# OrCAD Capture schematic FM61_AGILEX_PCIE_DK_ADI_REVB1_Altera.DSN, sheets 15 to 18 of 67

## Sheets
15 DDR4/DDRT Single DIMM CH2: size B
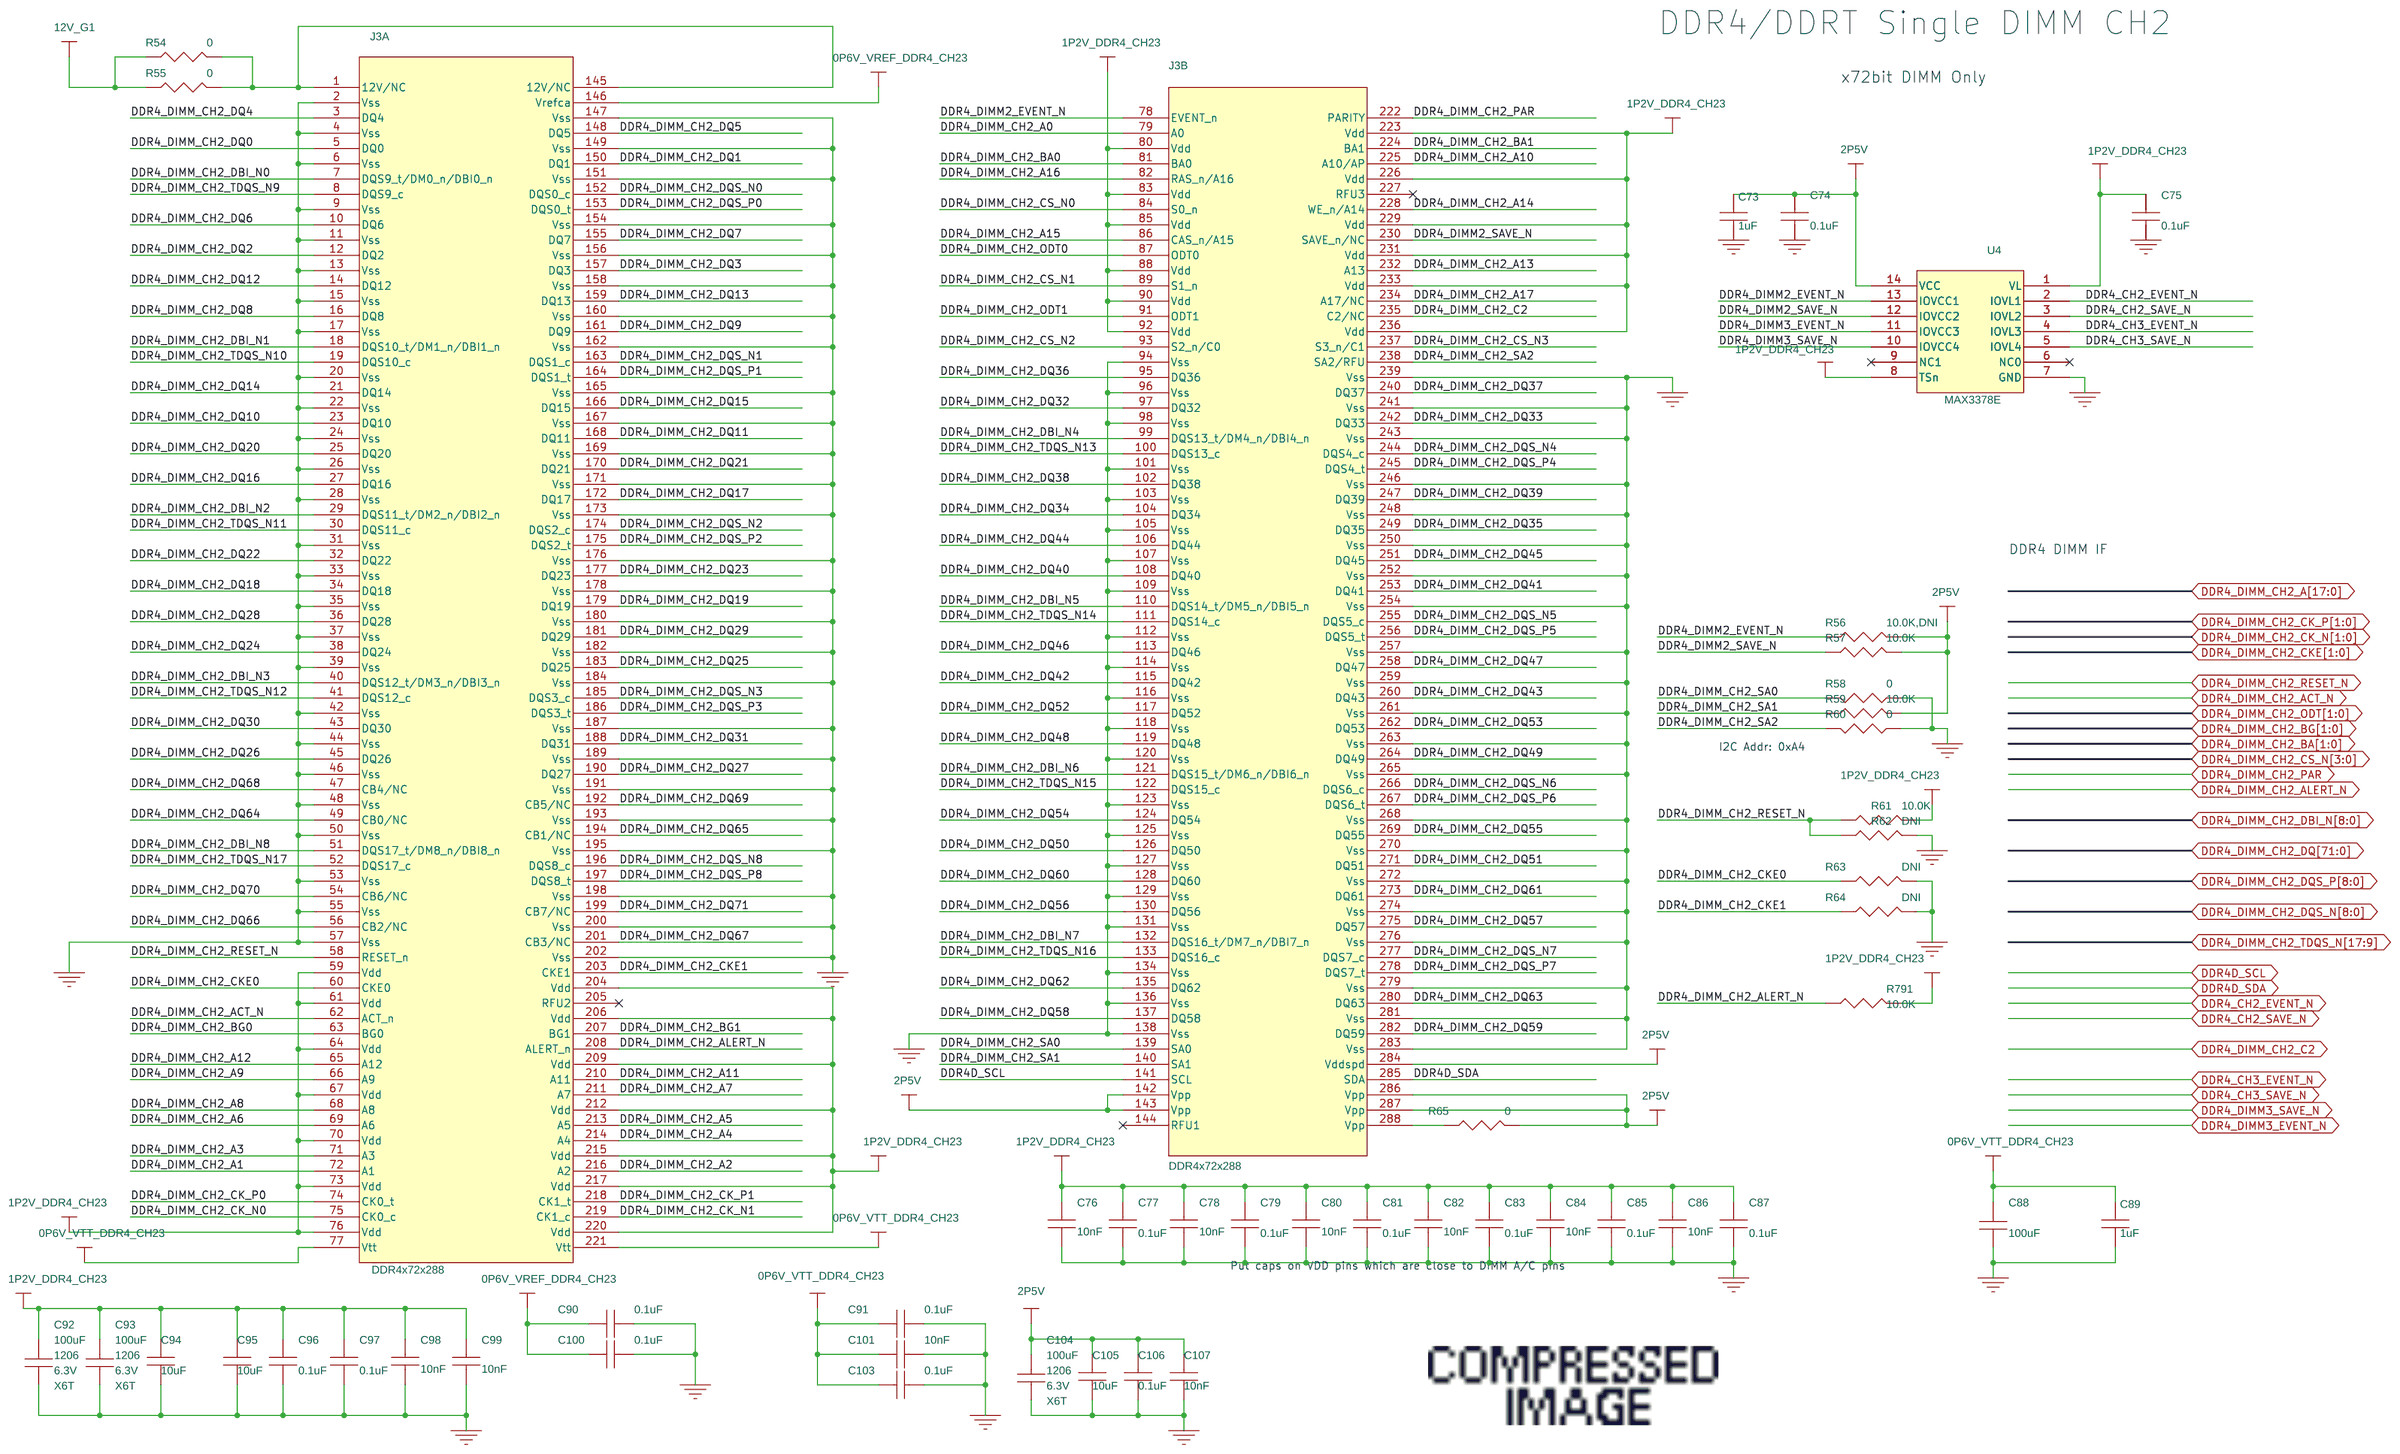
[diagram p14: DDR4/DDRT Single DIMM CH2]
16 FPGA BANK 2A: size B
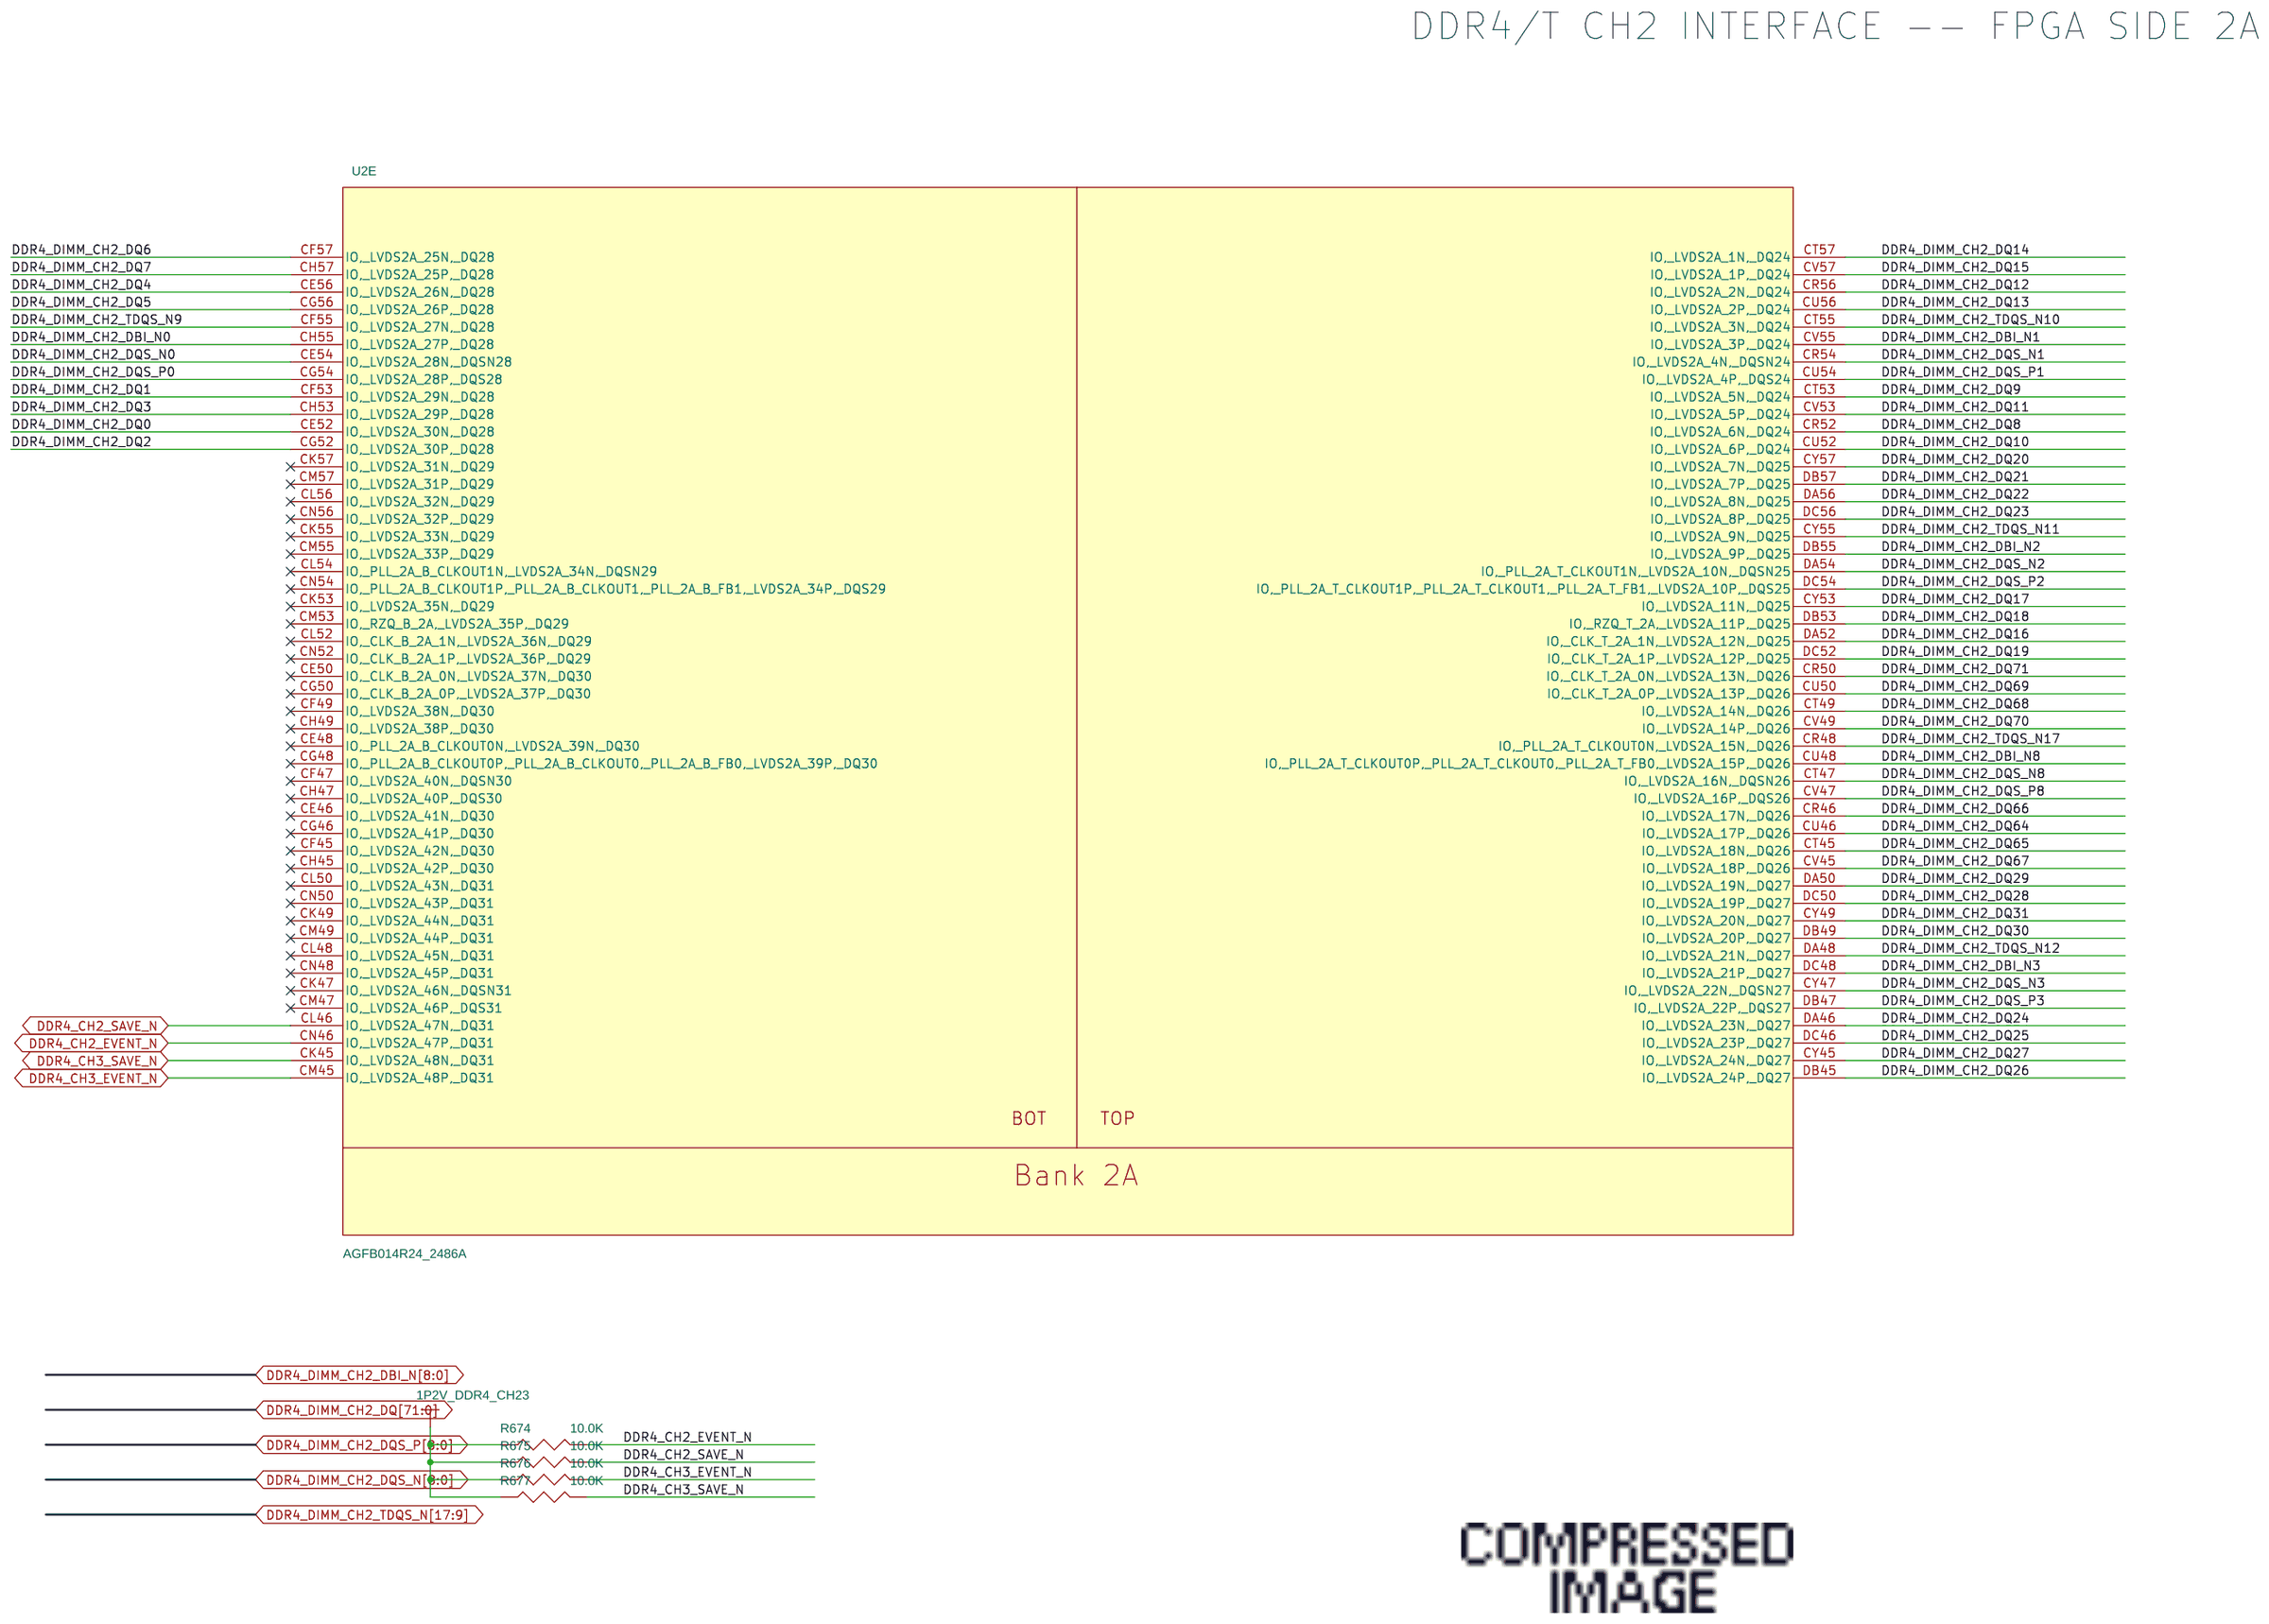
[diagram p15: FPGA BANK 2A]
17 FPGA BANK 2B: size B
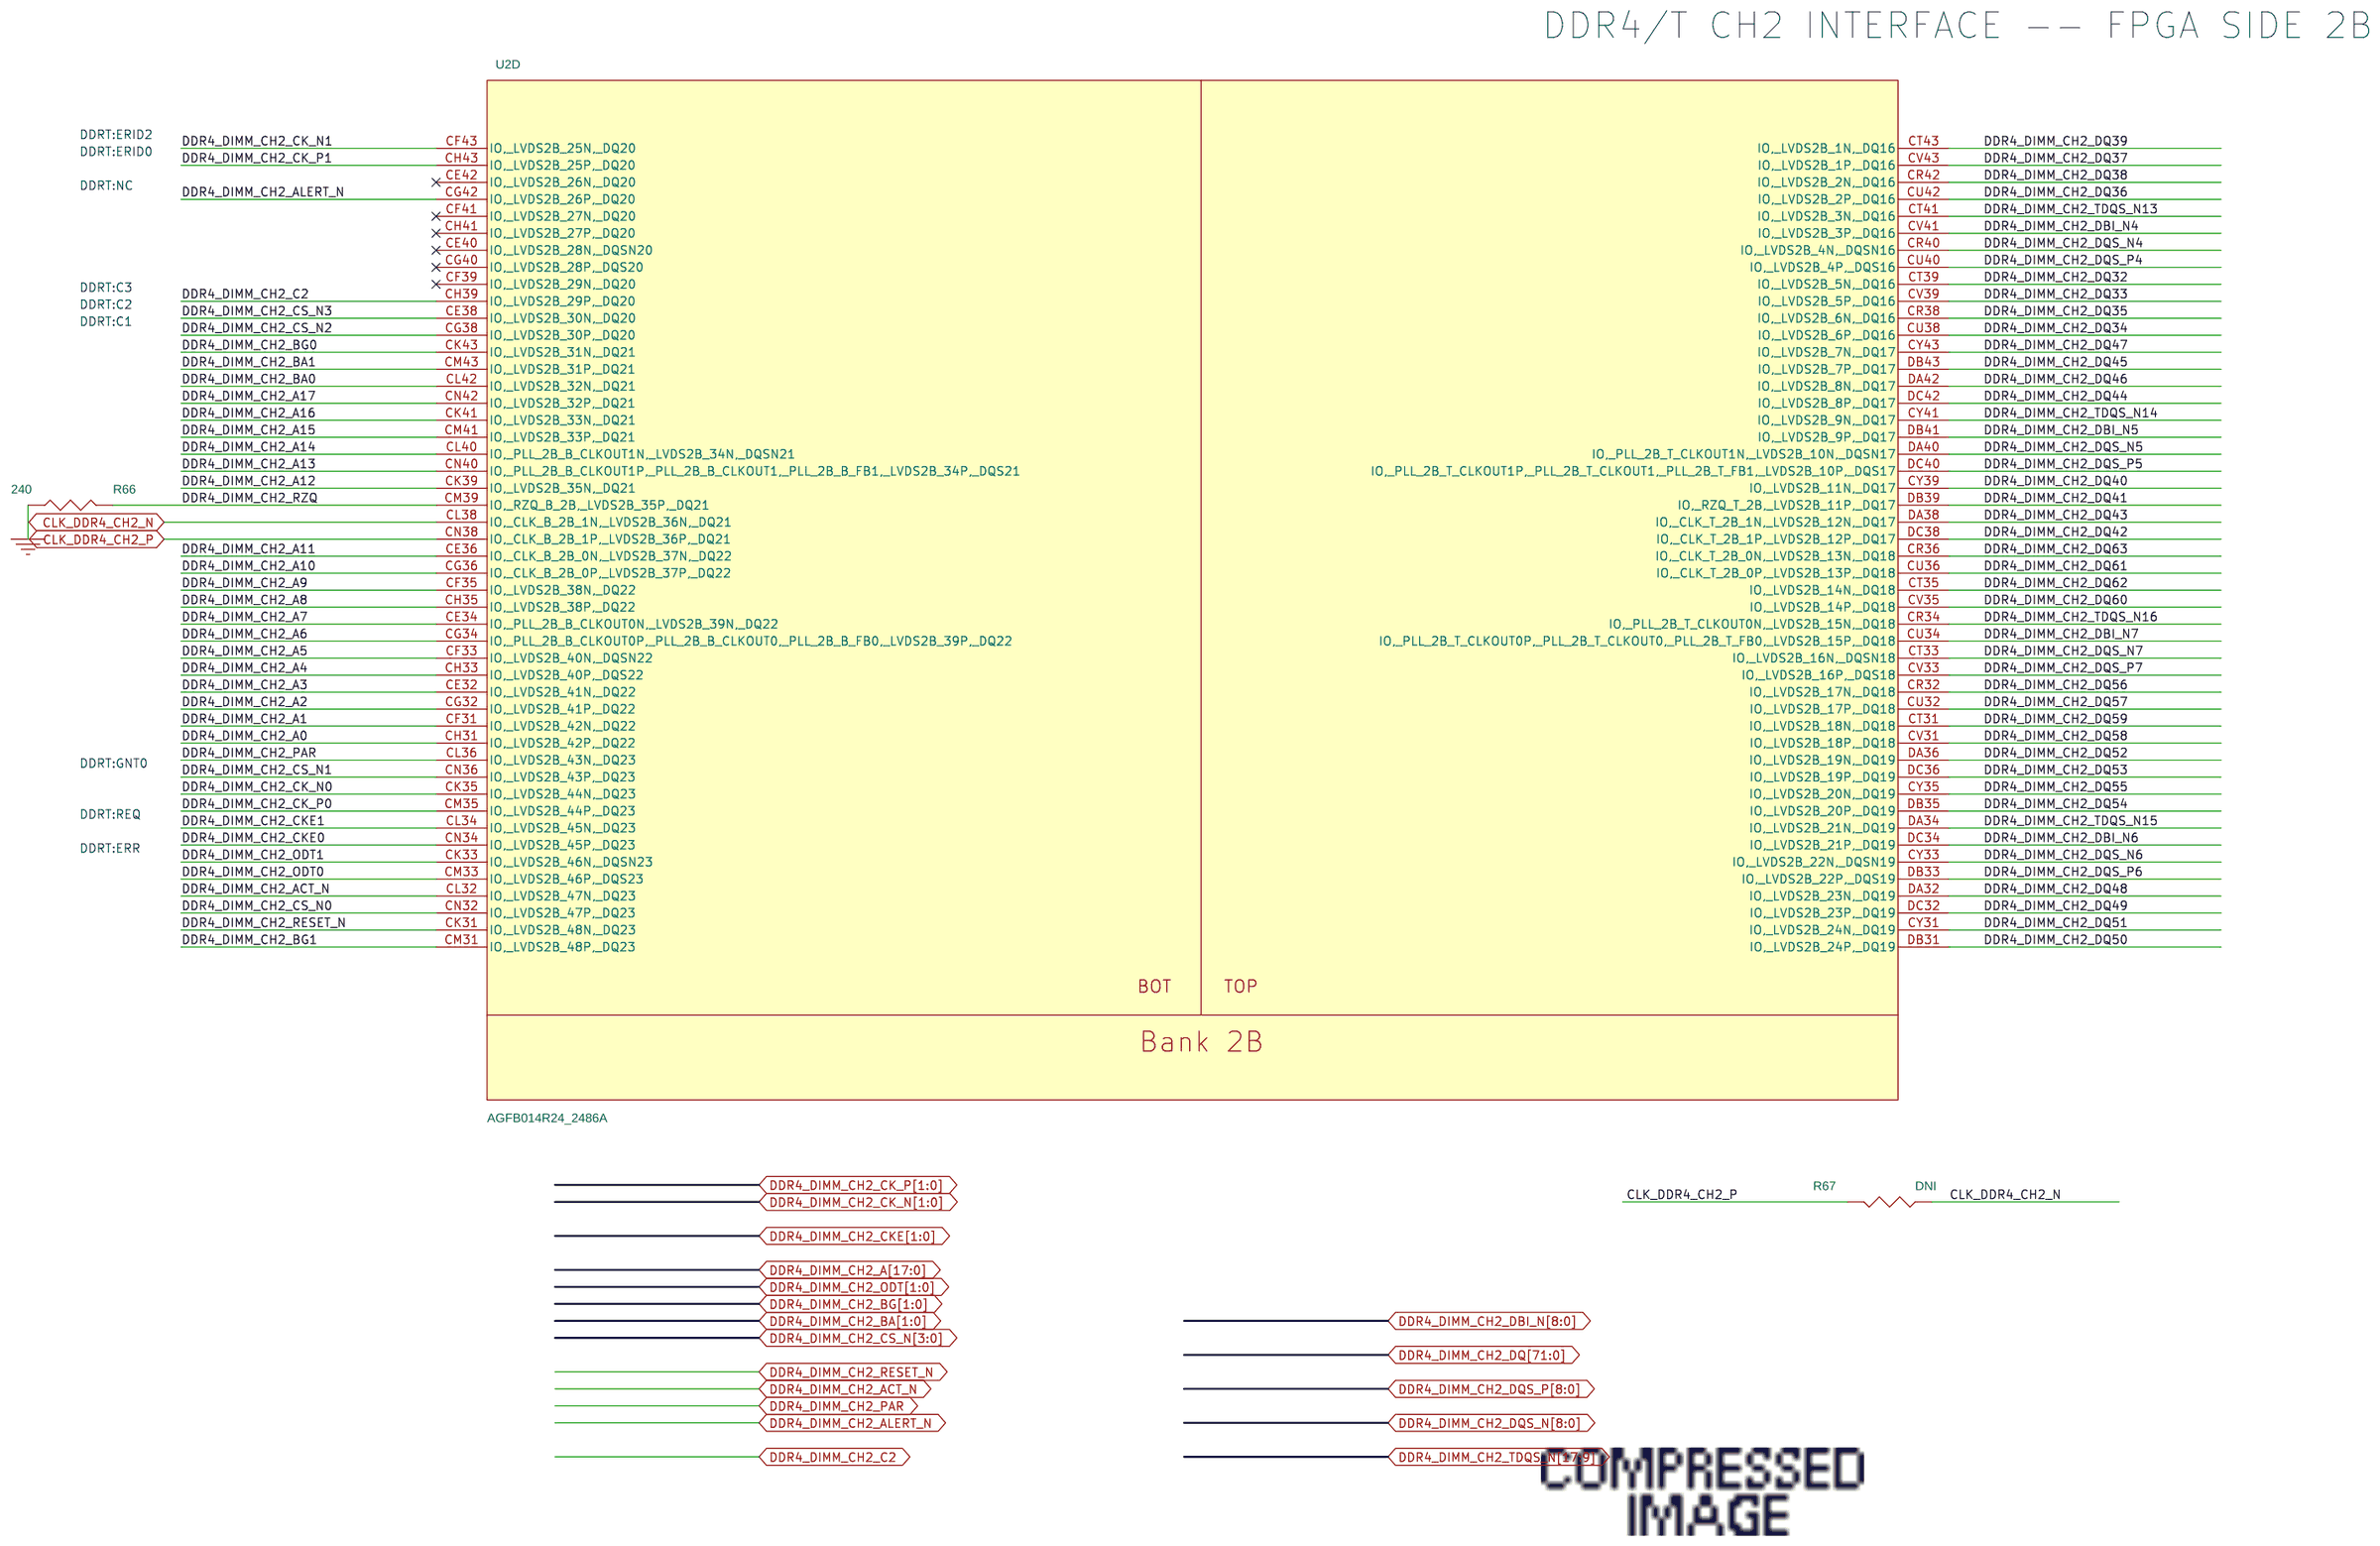
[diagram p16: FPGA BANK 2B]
18 DDR4/DDRT Single DIMM CH3: size B
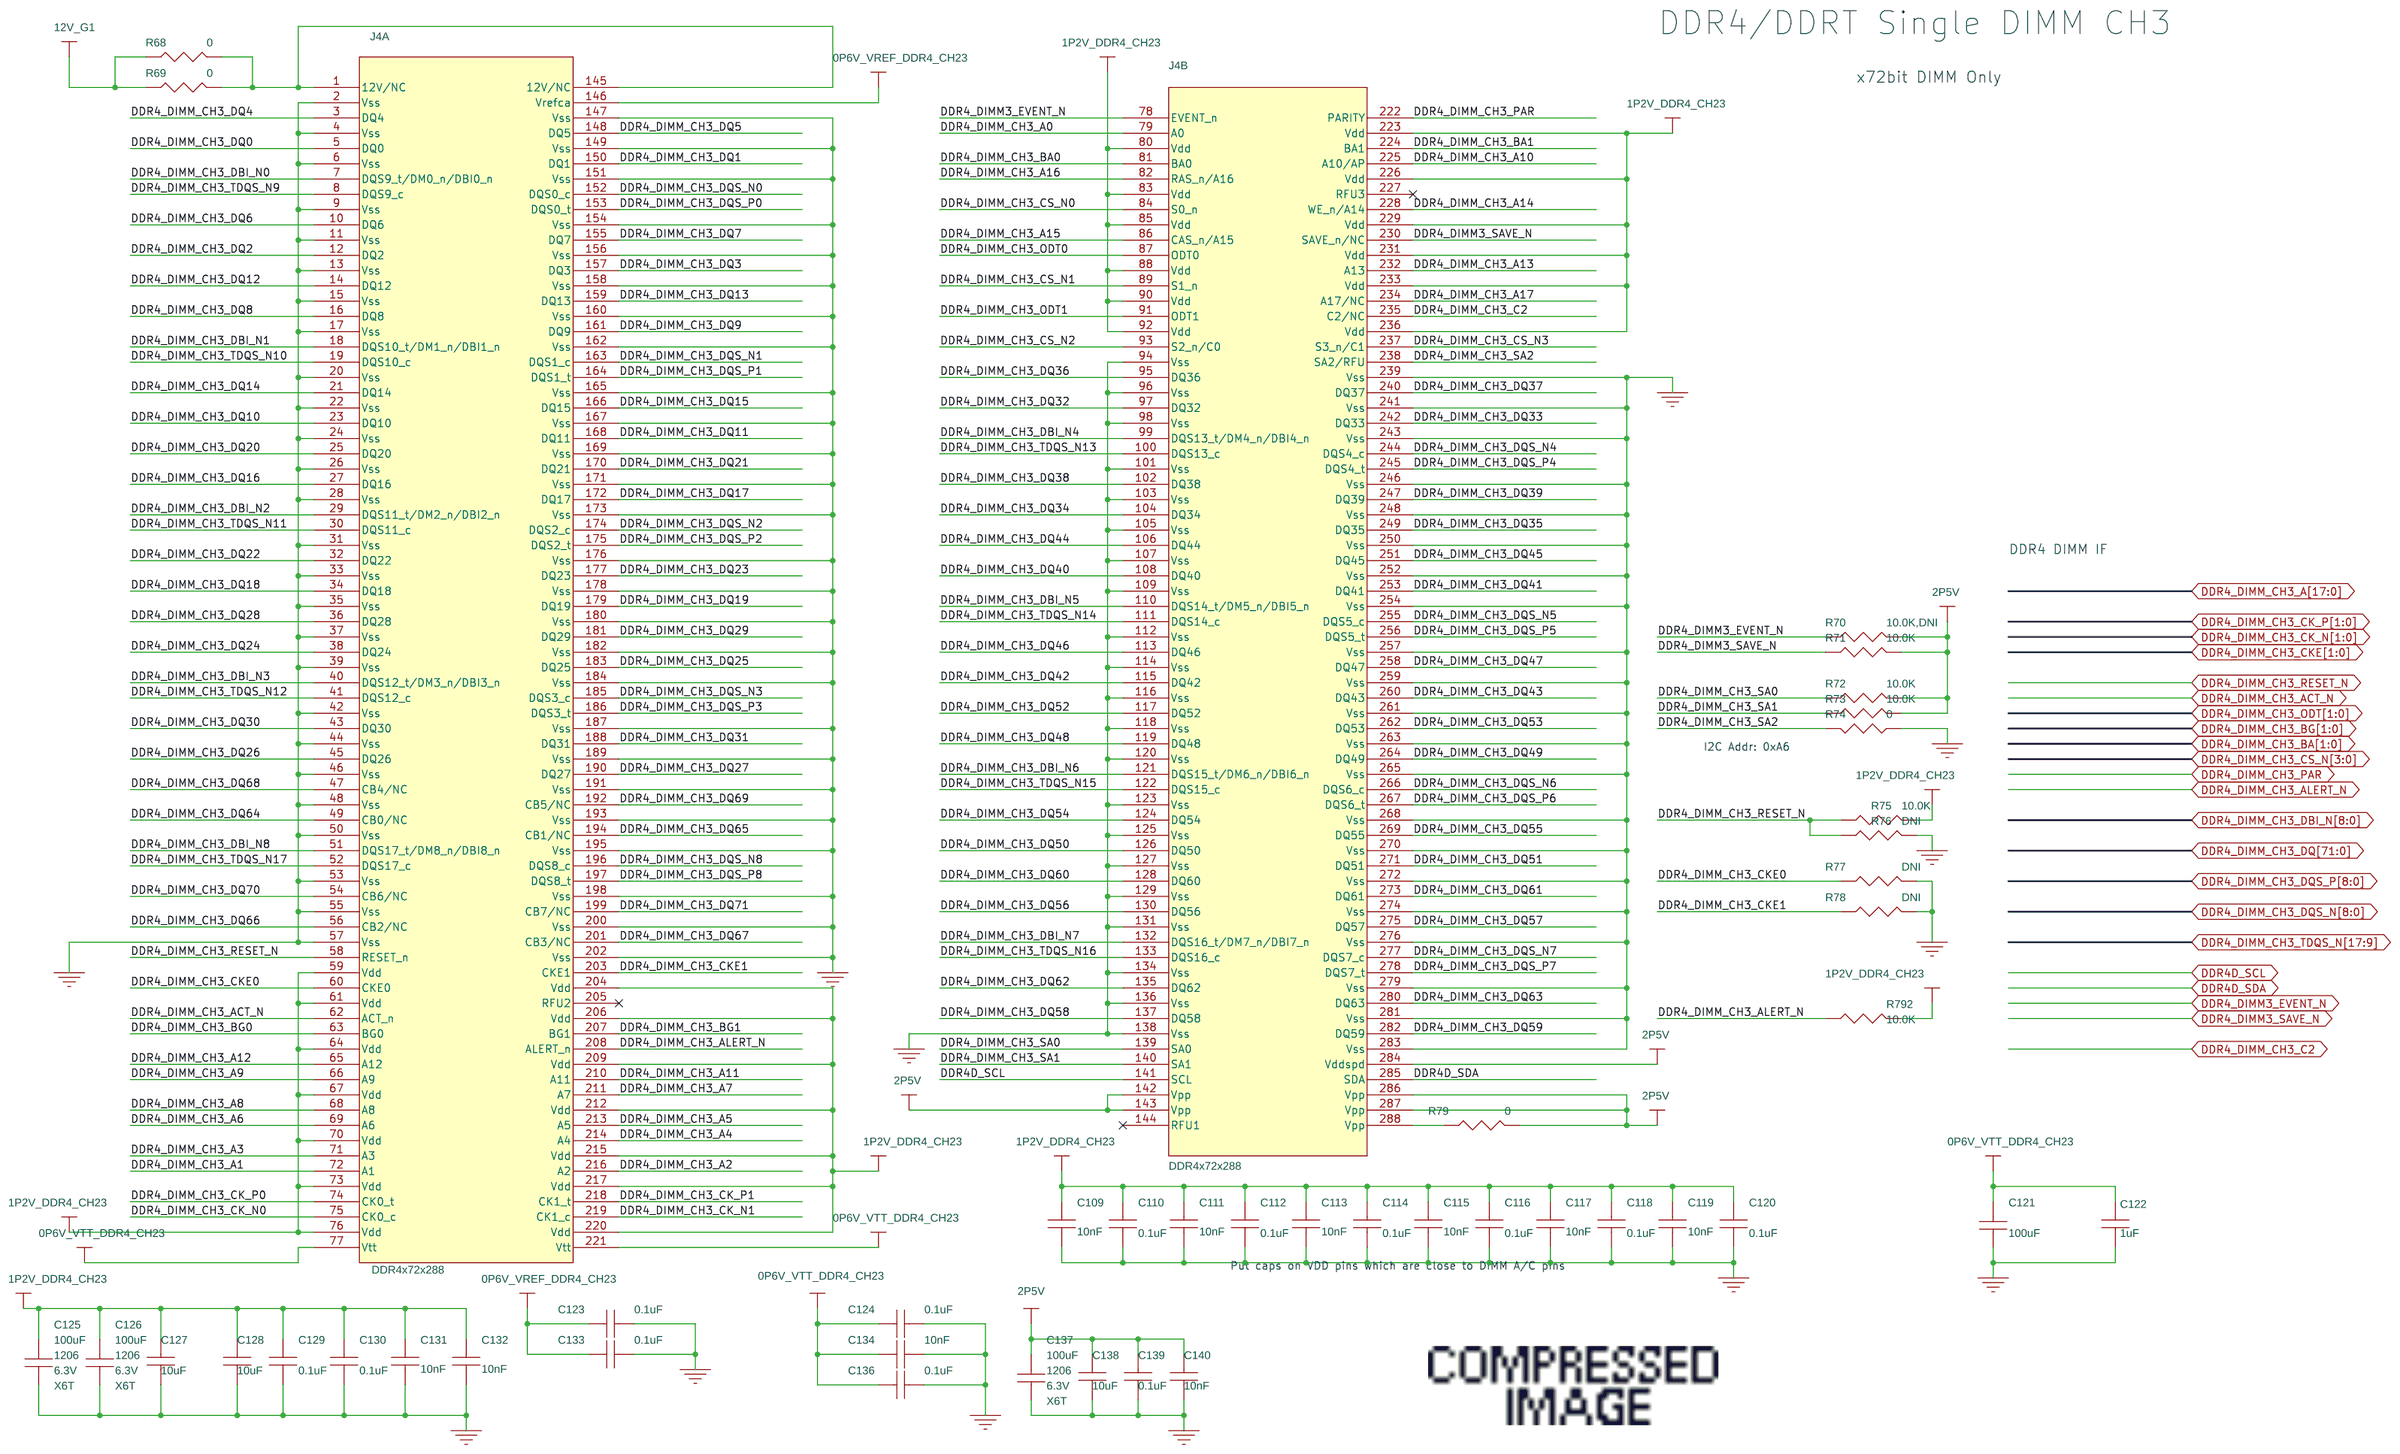
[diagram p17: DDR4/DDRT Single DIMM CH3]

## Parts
sheet DDR4/DDRT Single DIMM CH2
C73  1uF  [0402]
C74  0.1uF  [0402]
C75  0.1uF  [0402]
C76  10nF  [0402]
C77  0.1uF  [0402]
C78  10nF  [0402]
C79  0.1uF  [0402]
C80  10nF  [0402]
C81  0.1uF  [0402]
C82  10nF  [0402]
C83  0.1uF  [0402]
C84  10nF  [0402]
C85  0.1uF  [0402]
C86  10nF  [0402]
C87  0.1uF  [0402]
C88  100uF  [1206]
C89  1uF  [0402]
C90  0.1uF  [0402]
C91  0.1uF  [0402]
C92  100uF  [1206]
C93  100uF  [1206]
C94  10uF  [1210]
C95  10uF  [1210]
C96  0.1uF  [0402]
C97  0.1uF  [0402]
C98  10nF  [0402]
C99  10nF  [0402]
C100  0.1uF  [0402]
C101  10nF  [0402]
C103  0.1uF  [0402]
C104  100uF  [1206]
C105  10uF  [1210]
C106  0.1uF  [0402]
C107  10nF  [0402]
J3  DDR4x72x288  [DDR4DIMM_SMT]  (sections A,B)
R54  0  [1206]
R55  0  [1206]
R56  10.0K,DNI  [0402]
R57  10.0K  [0402]
R58  0  [0402]
R59  10.0K  [0402]
R60  0  [0402]
R61  10.0K  [0402]
R62  DNI  [0402]
R63  DNI  [0402]
R64  DNI  [0402]
R65  0  [0603]
R791  10.0K  [0402]
U4  MAX3378E  [TSSOP-14]
sheet DDR4/DDRT Single DIMM CH3
C109  10nF  [0402]
C110  0.1uF  [0402]
C111  10nF  [0402]
C112  0.1uF  [0402]
C113  10nF  [0402]
C114  0.1uF  [0402]
C115  10nF  [0402]
C116  0.1uF  [0402]
C117  10nF  [0402]
C118  0.1uF  [0402]
C119  10nF  [0402]
C120  0.1uF  [0402]
C121  100uF  [1206]
C122  1uF  [0402]
C123  0.1uF  [0402]
C124  0.1uF  [0402]
C125  100uF  [1206]
C126  100uF  [1206]
C127  10uF  [1210]
C128  10uF  [1210]
C129  0.1uF  [0402]
C130  0.1uF  [0402]
C131  10nF  [0402]
C132  10nF  [0402]
C133  0.1uF  [0402]
C134  10nF  [0402]
C136  0.1uF  [0402]
C137  100uF  [1206]
C138  10uF  [1210]
C139  0.1uF  [0402]
C140  10nF  [0402]
J4  DDR4x72x288  [DDR4DIMM_SMT]  (sections A,B)
R68  0  [1206]
R69  0  [1206]
R70  10.0K,DNI  [0402]
R71  10.0K  [0402]
R72  10.0K  [0402]
R73  10.0K  [0402]
R74  0  [0402]
R75  10.0K  [0402]
R76  DNI  [0402]
R77  DNI  [0402]
R78  DNI  [0402]
R79  0  [0603]
R792  10.0K  [0402]
sheet FPGA BANK 2A
R674  10.0K  [0402]
R675  10.0K  [0402]
R676  10.0K  [0402]
R677  10.0K  [0402]
sheet FPGA BANK 2B
R66  240  [0402]
R67  DNI  [0402]
sheet FPGA Gnd 2
U2  AGFB014R24_2486A  [FBGA2486A_HEX]  (sections A,B,C,D,E,F,G,H,I,J,K,L,M,N,O,P,Q,R,S,T,U,V,W,X)

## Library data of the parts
C73 C89 C122 = CAP: CAP, X5R, 1UF, 20%, 10V, 0402,; IPN: H67656-001; Item Num: P03-15479R; Lead Free Status: Yes; Manufacturer: Murata; Manufacturer Part Num: GRM155R61A105KE15D; Num Pins: 2; Part Class: CAPACITORS; RoHS Compliant: Yes; Voltage: 10V
C74 C75 C77 C79 C81 C83 C85 C87 C90 C91 C96 C97 C100 C103 C106 C110 C112 C114 C116 C118 C120 C123 C124 C129 C130 C133 C136 C139 = CAP: CAPC,Y5V,0402,0.1UF,25V,+80/-20%; Dielectric: Y5V; IPN: K13560-001; Item Num: P03-15057R; LIFECYCLE_PHASE: Active; Lead Free Status: Lead Free; MFR_LIFECYCLE: Active; Manufacturer: Murata; Manufacturer Part Num: GRM155F51E104ZA01D; Num Pins: 2; PART_SUBCLASS: CAPACITORS; Part Class: CAPACITORS; RATED_VOLTAGE: 25V; RoHS Compliant: RoHS Compliant; Tolerance: +80%/-20%
C76 C78 C84 C86 C98 C99 C109 C111 C113 C115 C117 C119 C131 C134 C140 = Cap_10000PF_50V_0402: CAP - CERAMIC, 10nF, 0402, 50V, Y5V; IPN: K30697-001; IPN No: K30697-001; Item Num: P03-15058R; Manufacturer Part Num: GRM155F51H103Z
C80 C82 C101 C107 C132 = Cap_10000PF_50V_0402: CAP - CERAMIC, 10nF, 0402, 50V, Y5V; IPN: K30697-001; Item Num: P03-15058R; Manufacturer Part Num: GRM155F51H103Z
C88 C92 C93 C104 C121 C125 C126 C137 = CAP: CAP CER 100UF 6.3V X6T 1206; AGILE_LINK: http://sj-agile9app/Agile/PLMServlet?action=OpenEmailObject&classid=10000&objid=257560276; IPN: H65271-004; Item Num: P03-18002R; LIFECYCLE_PHASE: Active; Lead Free Status: Lead Free; MFR_LIFECYCLE: Active; Manufacturer: Murata; Manufacturer Part Num: GRM31CD80J107ME39L; Num Pins: 2; PART_SUBCLASS: CAPACITORS; RATED_VOLTAGE: 6.3V; RoHS Compliant: RoHS Compliant; TOLERANCE: 20%; Temperature Coefficient: X6T
C94 C95 C105 C127 C128 C138 = CAP_10uF_+_-10%_25V_1210: CAP - CER, 10UF, 25V, 10%, X7R, 1210; Agile Part Description: CAP - CER, 10UF, 25V, 10%, X7R, 1210; IPN: G10603-003; Item Num: P03-15392R; Manufacturer Part Num: GRM32DR71E106KA12L
J3 J4 = DDR4x72x288_1: CONN SMT DDR4 288POS VERT; COMPGROUP: DDR4_PINGPONG_DIMMA; IPN: K21528-001; Item Num: P23-38871R; Manufacturer: Molex Inc; Manufacturer Part Num: 787301002
R54 R55 R68 R69 = RESISTOR: RES SMD 0 OHM JUMPER 3/4W 1206; AGILE_LINK: http://sj-agile9app/Agile/PLMServlet?action=OpenEmailObject&classid=10000&objid=146548997; IPN: A93552-015; Item Num: P02-17994R; LIFECYCLE_PHASE: Active; Lead Free Status: No; MFR_LIFECYCLE: Active; Manufacturer: Vishay Dale; Manufacturer Part Num: CRCW12060000Z0EAHP; Num Pins: 2; PART_SUBCLASS: RESISTORS; POWER: 3/4W; RoHS Compliant: Yes; TOLERANCE: +/-1%
R56 R70 = RESISTOR: RES,10.0K OHMS,1.0%,1/16W, 0402; AGILE_LINK: http://sj-agile9app/Agile/PLMServlet?action=OpenEmailObject&classid=10000&objid=146548997; IPN: A93548-034; Item Num: P02-11364R; LIFECYCLE_PHASE: Active; Lead Free Status: No; MFR_LIFECYCLE: Active; Manufacturer: Panasonic; Manufacturer Part Num: ERJ-2RKF1002X; Num Pins: 2; PART_SUBCLASS: RESISTORS; POWER: 1/16W; RESISTANCE: 10.0K; RoHS Compliant: Yes; TOLERANCE: +/-1%
R57 R59 R61 R71-R73 R75 R674-R677 R791 R792 = RESISTOR: RES,10.0K OHMS,1.0%,1/16W, 0402; AGILE_LINK: http://sj-agile9app/Agile/PLMServlet?action=OpenEmailObject&classid=10000&objid=146548997; IPN: A93548-034; Item Num: P02-11364R; LIFECYCLE_PHASE: Active; Lead Free Status: No; MFR_LIFECYCLE: Active; Manufacturer: Panasonic; Manufacturer Part Num: ERJ-2RKF1002X; Num Pins: 2; PART_SUBCLASS: RESISTORS; POWER: 1/16W; RoHS Compliant: Yes; TOLERANCE: +/-1%
R58 R60 R74 = RES_0_OHM_5%_1_16W_0402_SMD: IPN: H30887-001
R62-R64 R76-R78 = RESISTOR: RES ZERO OHM 1/16W 5% 0402 SMD; IPN: H30887-001; Item Num: P02-14020R; Lead Free Status: No; Manufacturer: Panasonic; Manufacturer Part Num: ERJ-2GE0R00X; Num Pins: 2; Part Class: RESISTORS; Price: 0; RoHS Compliant: Yes; Tolerance: 5%
R65 R79 = RESISTOR: RES - 0 OHM, 5% 0603 1/10W; IPN: E57868-001; Item Num: P02-14007R; Lead Free Status: No; Manufacturer: Panasonic; Manufacturer Part Num: ERJ-3GEY0R00V; Num Pins: 2; Part Class: RESISTORS; RoHS Compliant: Yes; Tolerance: 5%
U4 = MAX3378E_0: IC - QUAD LOW-VOLTAGE LEVEL TRANSLATOR, +/- 15KV, ESD-PROTECTED, 1UA, 16MBPS; IPN: C34337-001; Item Num: P01-13191R; Manufacturer: Maxim; Manufacturer Part Num: MAX3378EEUD
R66 = RESISTOR: RES - 240 OHM, 1/16W, 1%, 0402 SMD; IPN: K15783-001; Item Num: P02-15995R; LIFECYCLE_PHASE: Active; Lead Free Status: Lead Free; MFR_LIFECYCLE: Active; Manufacturer: Panasonic; Manufacturer Part Num: ERJ-2RKF2400X; Num Pins: 2; PART_SUBCLASS: RESISTORS; RoHS Compliant: RoHS Compliant
R67 = RESISTOR: RES,100 OHMS,1.0%,1/16W,0402; IPN: A36092-043; Item Num: P02-11381R; Lead Free Status: No; Manufacturer: Panasonic; Manufacturer Part Num: ERJ-2RKF1000X; Manufacturer's Part No.: ERJ-2RKF1000X; Num Pins: 2; Part Class: RESISTORS; Price: 0; RoHS Compliant: Yes
U2 = FM6_2486A_V1.5: IPN: 99AH52

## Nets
12V_G1: R54.1 R55.1 R68.1 R69.1 ; also on sheet 9 12 47 48 51 52 53 58
GND: C73.2 C74.2 C75.2 C76.2 C77.2 C78.2 C79.2 C80.2 C81.2 C82.2 C83.2 C84.2 C85.2 C86.2 C87.2 C88.1 C89.2 C90.2 C91.2 C92.1 C93.1 C94.2 C95.2 C96.2 C97.2 C98.2 C99.2 C100.2 C101.2 C103.2 C104.1 C105.2 C106.2 C107.2 C109.2 C110.2 C111.2 C112.2 C113.2 C114.2 C115.2 C116.2 C117.2 C118.2 C119.2 C120.2 C121.1 C122.2 C123.2 C124.2 C125.1 C126.1 C127.2 C128.2 C129.2 C130.2 C131.2 C132.2 C133.2 C134.2 C136.2 C137.1 C138.2 C139.2 C140.2 J3.2(Vss) J3.4(Vss) J3.6(Vss) J3.9(Vss) J3.11(Vss) J3.13(Vss) J3.15(Vss) J3.17(Vss) J3.20(Vss) J3.22(Vss) J3.24(Vss) J3.26(Vss) J3.28(Vss) J3.31(Vss) J3.33(Vss) J3.35(Vss) J3.37(Vss) J3.39(Vss) J3.42(Vss) J3.44(Vss) J3.46(Vss) J3.48(Vss) J3.50(Vss) J3.53(Vss) J3.55(Vss) J3.57(Vss) J3.94(Vss) J3.96(Vss) J3.98(Vss) J3.101(Vss) J3.103(Vss) J3.105(Vss) J3.107(Vss) J3.109(Vss) J3.112(Vss) J3.114(Vss) J3.116(Vss) J3.118(Vss) J3.120(Vss) J3.123(Vss) J3.125(Vss) J3.127(Vss) J3.129(Vss) J3.131(Vss) J3.134(Vss) J3.136(Vss) J3.138(Vss) J3.147(Vss) J3.149(Vss) J3.151(Vss) J3.154(Vss) J3.156(Vss) J3.158(Vss) J3.160(Vss) J3.162(Vss) J3.165(Vss) J3.167(Vss) J3.169(Vss) J3.171(Vss) J3.173(Vss) J3.176(Vss) J3.178(Vss) J3.180(Vss) J3.182(Vss) J3.184(Vss) J3.187(Vss) J3.189(Vss) J3.191(Vss) J3.193(Vss) J3.195(Vss) J3.198(Vss) J3.200(Vss) J3.202(Vss) J3.239(Vss) J3.241(Vss) J3.243(Vss) J3.246(Vss) J3.248(Vss) J3.250(Vss) J3.252(Vss) J3.254(Vss) J3.257(Vss) J3.259(Vss) J3.261(Vss) J3.263(Vss) J3.265(Vss) J3.268(Vss) J3.270(Vss) J3.272(Vss) J3.274(Vss) J3.276(Vss) J3.279(Vss) J3.281(Vss) J3.283(Vss) J4.2(Vss) J4.4(Vss) J4.6(Vss) J4.9(Vss) J4.11(Vss) J4.13(Vss) J4.15(Vss) J4.17(Vss) J4.20(Vss) J4.22(Vss) J4.24(Vss) J4.26(Vss) J4.28(Vss) J4.31(Vss) J4.33(Vss) J4.35(Vss) J4.37(Vss) J4.39(Vss) J4.42(Vss) J4.44(Vss) J4.46(Vss) J4.48(Vss) J4.50(Vss) J4.53(Vss) J4.55(Vss) J4.57(Vss) J4.94(Vss) J4.96(Vss) J4.98(Vss) J4.101(Vss) J4.103(Vss) J4.105(Vss) J4.107(Vss) J4.109(Vss) J4.112(Vss) J4.114(Vss) J4.116(Vss) J4.118(Vss) J4.120(Vss) J4.123(Vss) J4.125(Vss) J4.127(Vss) J4.129(Vss) J4.131(Vss) J4.134(Vss) J4.136(Vss) J4.138(Vss) J4.147(Vss) J4.149(Vss) J4.151(Vss) J4.154(Vss) J4.156(Vss) J4.158(Vss) J4.160(Vss) J4.162(Vss) J4.165(Vss) J4.167(Vss) J4.169(Vss) J4.171(Vss) J4.173(Vss) J4.176(Vss) J4.178(Vss) J4.180(Vss) J4.182(Vss) J4.184(Vss) J4.187(Vss) J4.189(Vss) J4.191(Vss) J4.193(Vss) J4.195(Vss) J4.198(Vss) J4.200(Vss) J4.202(Vss) J4.239(Vss) J4.241(Vss) J4.243(Vss) J4.246(Vss) J4.248(Vss) J4.250(Vss) J4.252(Vss) J4.254(Vss) J4.257(Vss) J4.259(Vss) J4.261(Vss) J4.263(Vss) J4.265(Vss) J4.268(Vss) J4.270(Vss) J4.272(Vss) J4.274(Vss) J4.276(Vss) J4.279(Vss) J4.281(Vss) J4.283(Vss) R58.1 R60.1 R62.1 R63.1 R64.1 R66.1 R74.1 R76.1 R77.1 R78.1 U4.7(GND) ; also on sheet 9 11 12 13 14 20 21 22 23 24 25 26 28 29 30 31 32 34 35 36 37 38 39 40 41 42 43 44 45 46 47 48 49 50 51 52 53 54 55 56 57 58 59 60 61 62 63 64 65 66
0p6V_VREF_DDR4_CH23: C90.1 C100.1 C123.1 C133.1 J3.146(Vrefca) J4.146(Vrefca) ; also on sheet 34 62
0p6V_VTT_DDR4_CH23: C88.2 C89.1 C91.1 C101.1 C103.1 C121.2 C122.1 C124.1 C134.1 C136.1 J3.77(Vtt) J3.221(Vtt) J4.77(Vtt) J4.221(Vtt) ; also on sheet 62
1p2V_DDR4_CH23: C75.1 C76.1 C77.1 C78.1 C79.1 C80.1 C81.1 C82.1 C83.1 C84.1 C85.1 C86.1 C87.1 C92.2 C93.2 C94.1 C95.1 C96.1 C97.1 C98.1 C99.1 C109.1 C110.1 C111.1 C112.1 C113.1 C114.1 C115.1 C116.1 C117.1 C118.1 C119.1 C120.1 C125.2 C126.2 C127.1 C128.1 C129.1 C130.1 C131.1 C132.1 J3.59(Vdd) J3.61(Vdd) J3.64(Vdd) J3.67(Vdd) J3.70(Vdd) J3.73(Vdd) J3.76(Vdd) J3.80(Vdd) J3.83(Vdd) J3.85(Vdd) J3.88(Vdd) J3.90(Vdd) J3.92(Vdd) J3.204(Vdd) J3.206(Vdd) J3.209(Vdd) J3.212(Vdd) J3.215(Vdd) J3.217(Vdd) J3.220(Vdd) J3.223(Vdd) J3.226(Vdd) J3.229(Vdd) J3.231(Vdd) J3.233(Vdd) J3.236(Vdd) J4.59(Vdd) J4.61(Vdd) J4.64(Vdd) J4.67(Vdd) J4.70(Vdd) J4.73(Vdd) J4.76(Vdd) J4.80(Vdd) J4.83(Vdd) J4.85(Vdd) J4.88(Vdd) J4.90(Vdd) J4.92(Vdd) J4.204(Vdd) J4.206(Vdd) J4.209(Vdd) J4.212(Vdd) J4.215(Vdd) J4.217(Vdd) J4.220(Vdd) J4.223(Vdd) J4.226(Vdd) J4.229(Vdd) J4.231(Vdd) J4.233(Vdd) J4.236(Vdd) R61.2 R75.2 R674.1 R675.1 R676.1 R677.1 R791.2 R792.2 U4.1(VL) U4.8(TSn) ; also on sheet 19 25 34 46 61 62 66
2p5V: C73.1 C74.1 C104.2 C105.1 C106.1 C107.1 C137.2 C138.1 C139.1 C140.1 J3.142(Vpp) J3.143(Vpp) J3.284(Vddspd) J3.286(Vpp) J3.287(Vpp) J4.142(Vpp) J4.143(Vpp) J4.284(Vddspd) J4.286(Vpp) J4.287(Vpp) R56.2 R57.2 R59.2 R65.1 R70.2 R71.2 R72.2 R73.2 R79.1 U4.14(VCC) ; also on sheet 9 12 21 34 38 63
CLK_DDR4_CH2_N: R67.1 U2.CL38(IO,_CLK_B_2B_1N,_LVDS2B_36N,_DQ21) ; also on sheet 38
CLK_DDR4_CH2_P: R67.2 U2.CN38(IO,_CLK_B_2B_1P,_LVDS2B_36P,_DQ21) ; also on sheet 38
DDR4_CH2_EVENT_N: R674.2 U2.CN46(IO,_LVDS2A_47P,_DQ31) U4.2(IOVL1)
DDR4_CH2_SAVE_N: R675.2 U2.CL46(IO,_LVDS2A_47N,_DQ31) U4.3(IOVL2)
DDR4_CH3_EVENT_N: R676.2 U2.CM45(IO,_LVDS2A_48P,_DQ31) U4.4(IOVL3)
DDR4_CH3_SAVE_N: R677.2 U2.CK45(IO,_LVDS2A_48N,_DQ31) U4.5(IOVL4)
DDR4_DIMM2_EVENT_N: J3.78(EVENT_n) R56.1 U4.13(IOVCC1)
DDR4_DIMM2_SAVE_N: J3.230(SAVE_n/NC) R57.1 U4.12(IOVCC2)
DDR4_DIMM3_EVENT_N: J4.78(EVENT_n) R70.1 U4.11(IOVCC3)
DDR4_DIMM3_SAVE_N: J4.230(SAVE_n/NC) R71.1 U4.10(IOVCC4)
DDR4_DIMM_CH2_A0: J3.79(A0) U2.CH31(IO,_LVDS2B_42P,_DQ22)
DDR4_DIMM_CH2_A1: J3.72(A1) U2.CF31(IO,_LVDS2B_42N,_DQ22)
DDR4_DIMM_CH2_A2: J3.216(A2) U2.CG32(IO,_LVDS2B_41P,_DQ22)
DDR4_DIMM_CH2_A3: J3.71(A3) U2.CE32(IO,_LVDS2B_41N,_DQ22)
DDR4_DIMM_CH2_A4: J3.214(A4) U2.CH33(IO,_LVDS2B_40P,_DQS22)
DDR4_DIMM_CH2_A5: J3.213(A5) U2.CF33(IO,_LVDS2B_40N,_DQSN22)
DDR4_DIMM_CH2_A6: J3.69(A6) U2.CG34(IO,_PLL_2B_B_CLKOUT0P,_PLL_2B_B_CLKOUT0,_PLL_2B_B_FB0,_LVDS2B_39P,_DQ22)
DDR4_DIMM_CH2_A7: J3.211(A7) U2.CE34(IO,_PLL_2B_B_CLKOUT0N,_LVDS2B_39N,_DQ22)
DDR4_DIMM_CH2_A8: J3.68(A8) U2.CH35(IO,_LVDS2B_38P,_DQ22)
DDR4_DIMM_CH2_A9: J3.66(A9) U2.CF35(IO,_LVDS2B_38N,_DQ22)
DDR4_DIMM_CH2_A10: J3.225(A10/AP) U2.CG36(IO,_CLK_B_2B_0P,_LVDS2B_37P,_DQ22)
DDR4_DIMM_CH2_A11: J3.210(A11) U2.CE36(IO,_CLK_B_2B_0N,_LVDS2B_37N,_DQ22)
DDR4_DIMM_CH2_A12: J3.65(A12) U2.CK39(IO,_LVDS2B_35N,_DQ21)
DDR4_DIMM_CH2_A13: J3.232(A13) U2.CN40(IO,_PLL_2B_B_CLKOUT1P,_PLL_2B_B_CLKOUT1,_PLL_2B_B_FB1,_LVDS2B_34P,_DQS21)
DDR4_DIMM_CH2_A14: J3.228(WE_n/A14) U2.CL40(IO,_PLL_2B_B_CLKOUT1N,_LVDS2B_34N,_DQSN21)
DDR4_DIMM_CH2_A15: J3.86(CAS_n/A15) U2.CM41(IO,_LVDS2B_33P,_DQ21)
DDR4_DIMM_CH2_A16: J3.82(RAS_n/A16) U2.CK41(IO,_LVDS2B_33N,_DQ21)
DDR4_DIMM_CH2_A17: J3.234(A17/NC) U2.CN42(IO,_LVDS2B_32P,_DQ21)
DDR4_DIMM_CH2_ACT_N: J3.62(ACT_n) U2.CL32(IO,_LVDS2B_47N,_DQ23)
DDR4_DIMM_CH2_ALERT_N: J3.208(ALERT_n) R791.1 U2.CG42(IO,_LVDS2B_26P,_DQ20)
DDR4_DIMM_CH2_BA0: J3.81(BA0) U2.CL42(IO,_LVDS2B_32N,_DQ21)
DDR4_DIMM_CH2_BA1: J3.224(BA1) U2.CM43(IO,_LVDS2B_31P,_DQ21)
DDR4_DIMM_CH2_BG0: J3.63(BG0) U2.CK43(IO,_LVDS2B_31N,_DQ21)
DDR4_DIMM_CH2_BG1: J3.207(BG1) U2.CM31(IO,_LVDS2B_48P,_DQ23)
DDR4_DIMM_CH2_C2: J3.235(C2/NC) U2.CH39(IO,_LVDS2B_29P,_DQ20)
DDR4_DIMM_CH2_CK_N0: J3.75(CK0_c) U2.CK35(IO,_LVDS2B_44N,_DQ23)
DDR4_DIMM_CH2_CK_N1: J3.219(CK1_c) U2.CF43(IO,_LVDS2B_25N,_DQ20)
DDR4_DIMM_CH2_CK_P0: J3.74(CK0_t) U2.CM35(IO,_LVDS2B_44P,_DQ23)
DDR4_DIMM_CH2_CK_P1: J3.218(CK1_t) U2.CH43(IO,_LVDS2B_25P,_DQ20)
DDR4_DIMM_CH2_CKE0: J3.60(CKE0) R63.2 U2.CN34(IO,_LVDS2B_45P,_DQ23)
DDR4_DIMM_CH2_CKE1: J3.203(CKE1) R64.2 U2.CL34(IO,_LVDS2B_45N,_DQ23)
DDR4_DIMM_CH2_CS_N0: J3.84(S0_n) U2.CN32(IO,_LVDS2B_47P,_DQ23)
DDR4_DIMM_CH2_CS_N1: J3.89(S1_n) U2.CN36(IO,_LVDS2B_43P,_DQ23)
DDR4_DIMM_CH2_CS_N2: J3.93(S2_n/C0) U2.CG38(IO,_LVDS2B_30P,_DQ20)
DDR4_DIMM_CH2_CS_N3: J3.237(S3_n/C1) U2.CE38(IO,_LVDS2B_30N,_DQ20)
DDR4_DIMM_CH2_DBI_N0: J3.7(DQS9_t/DM0_n/DBI0_n) U2.CH55(IO,_LVDS2A_27P,_DQ28)
DDR4_DIMM_CH2_DBI_N1: J3.18(DQS10_t/DM1_n/DBI1_n) U2.CV55(IO,_LVDS2A_3P,_DQ24)
DDR4_DIMM_CH2_DBI_N2: J3.29(DQS11_t/DM2_n/DBI2_n) U2.DB55(IO,_LVDS2A_9P,_DQ25)
DDR4_DIMM_CH2_DBI_N3: J3.40(DQS12_t/DM3_n/DBI3_n) U2.DC48(IO,_LVDS2A_21P,_DQ27)
DDR4_DIMM_CH2_DBI_N4: J3.99(DQS13_t/DM4_n/DBI4_n) U2.CV41(IO,_LVDS2B_3P,_DQ16)
DDR4_DIMM_CH2_DBI_N5: J3.110(DQS14_t/DM5_n/DBI5_n) U2.DB41(IO,_LVDS2B_9P,_DQ17)
DDR4_DIMM_CH2_DBI_N6: J3.121(DQS15_t/DM6_n/DBI6_n) U2.DC34(IO,_LVDS2B_21P,_DQ19)
DDR4_DIMM_CH2_DBI_N7: J3.132(DQS16_t/DM7_n/DBI7_n) U2.CU34(IO,_PLL_2B_T_CLKOUT0P,_PLL_2B_T_CLKOUT0,_PLL_2B_T_FB0,_LVDS2B_15P,_DQ18)
DDR4_DIMM_CH2_DBI_N8: J3.51(DQS17_t/DM8_n/DBI8_n) U2.CU48(IO,_PLL_2A_T_CLKOUT0P,_PLL_2A_T_CLKOUT0,_PLL_2A_T_FB0,_LVDS2A_15P,_DQ26)
DDR4_DIMM_CH2_DQ0: J3.5(DQ0) U2.CE52(IO,_LVDS2A_30N,_DQ28)
DDR4_DIMM_CH2_DQ1: J3.150(DQ1) U2.CF53(IO,_LVDS2A_29N,_DQ28)
DDR4_DIMM_CH2_DQ2: J3.12(DQ2) U2.CG52(IO,_LVDS2A_30P,_DQ28)
DDR4_DIMM_CH2_DQ3: J3.157(DQ3) U2.CH53(IO,_LVDS2A_29P,_DQ28)
DDR4_DIMM_CH2_DQ4: J3.3(DQ4) U2.CE56(IO,_LVDS2A_26N,_DQ28)
DDR4_DIMM_CH2_DQ5: J3.148(DQ5) U2.CG56(IO,_LVDS2A_26P,_DQ28)
DDR4_DIMM_CH2_DQ6: J3.10(DQ6) U2.CF57(IO,_LVDS2A_25N,_DQ28)
DDR4_DIMM_CH2_DQ7: J3.155(DQ7) U2.CH57(IO,_LVDS2A_25P,_DQ28)
DDR4_DIMM_CH2_DQ8: J3.16(DQ8) U2.CR52(IO,_LVDS2A_6N,_DQ24)
DDR4_DIMM_CH2_DQ9: J3.161(DQ9) U2.CT53(IO,_LVDS2A_5N,_DQ24)
DDR4_DIMM_CH2_DQ10: J3.23(DQ10) U2.CU52(IO,_LVDS2A_6P,_DQ24)
DDR4_DIMM_CH2_DQ11: J3.168(DQ11) U2.CV53(IO,_LVDS2A_5P,_DQ24)
DDR4_DIMM_CH2_DQ12: J3.14(DQ12) U2.CR56(IO,_LVDS2A_2N,_DQ24)
DDR4_DIMM_CH2_DQ13: J3.159(DQ13) U2.CU56(IO,_LVDS2A_2P,_DQ24)
DDR4_DIMM_CH2_DQ14: J3.21(DQ14) U2.CT57(IO,_LVDS2A_1N,_DQ24)
DDR4_DIMM_CH2_DQ15: J3.166(DQ15) U2.CV57(IO,_LVDS2A_1P,_DQ24)
DDR4_DIMM_CH2_DQ16: J3.27(DQ16) U2.DA52(IO,_CLK_T_2A_1N,_LVDS2A_12N,_DQ25)
DDR4_DIMM_CH2_DQ17: J3.172(DQ17) U2.CY53(IO,_LVDS2A_11N,_DQ25)
DDR4_DIMM_CH2_DQ18: J3.34(DQ18) U2.DB53(IO,_RZQ_T_2A,_LVDS2A_11P,_DQ25)
DDR4_DIMM_CH2_DQ19: J3.179(DQ19) U2.DC52(IO,_CLK_T_2A_1P,_LVDS2A_12P,_DQ25)
DDR4_DIMM_CH2_DQ20: J3.25(DQ20) U2.CY57(IO,_LVDS2A_7N,_DQ25)
DDR4_DIMM_CH2_DQ21: J3.170(DQ21) U2.DB57(IO,_LVDS2A_7P,_DQ25)
DDR4_DIMM_CH2_DQ22: J3.32(DQ22) U2.DA56(IO,_LVDS2A_8N,_DQ25)
DDR4_DIMM_CH2_DQ23: J3.177(DQ23) U2.DC56(IO,_LVDS2A_8P,_DQ25)
DDR4_DIMM_CH2_DQ24: J3.38(DQ24) U2.DA46(IO,_LVDS2A_23N,_DQ27)
DDR4_DIMM_CH2_DQ25: J3.183(DQ25) U2.DC46(IO,_LVDS2A_23P,_DQ27)
DDR4_DIMM_CH2_DQ26: J3.45(DQ26) U2.DB45(IO,_LVDS2A_24P,_DQ27)
DDR4_DIMM_CH2_DQ27: J3.190(DQ27) U2.CY45(IO,_LVDS2A_24N,_DQ27)
DDR4_DIMM_CH2_DQ28: J3.36(DQ28) U2.DC50(IO,_LVDS2A_19P,_DQ27)
DDR4_DIMM_CH2_DQ29: J3.181(DQ29) U2.DA50(IO,_LVDS2A_19N,_DQ27)
DDR4_DIMM_CH2_DQ30: J3.43(DQ30) U2.DB49(IO,_LVDS2A_20P,_DQ27)
DDR4_DIMM_CH2_DQ31: J3.188(DQ31) U2.CY49(IO,_LVDS2A_20N,_DQ27)
DDR4_DIMM_CH2_DQ32: J3.97(DQ32) U2.CT39(IO,_LVDS2B_5N,_DQ16)
DDR4_DIMM_CH2_DQ33: J3.242(DQ33) U2.CV39(IO,_LVDS2B_5P,_DQ16)
DDR4_DIMM_CH2_DQ34: J3.104(DQ34) U2.CU38(IO,_LVDS2B_6P,_DQ16)
DDR4_DIMM_CH2_DQ35: J3.249(DQ35) U2.CR38(IO,_LVDS2B_6N,_DQ16)
DDR4_DIMM_CH2_DQ36: J3.95(DQ36) U2.CU42(IO,_LVDS2B_2P,_DQ16)
DDR4_DIMM_CH2_DQ37: J3.240(DQ37) U2.CV43(IO,_LVDS2B_1P,_DQ16)
DDR4_DIMM_CH2_DQ38: J3.102(DQ38) U2.CR42(IO,_LVDS2B_2N,_DQ16)
DDR4_DIMM_CH2_DQ39: J3.247(DQ39) U2.CT43(IO,_LVDS2B_1N,_DQ16)
DDR4_DIMM_CH2_DQ40: J3.108(DQ40) U2.CY39(IO,_LVDS2B_11N,_DQ17)
DDR4_DIMM_CH2_DQ41: J3.253(DQ41) U2.DB39(IO,_RZQ_T_2B,_LVDS2B_11P,_DQ17)
DDR4_DIMM_CH2_DQ42: J3.115(DQ42) U2.DC38(IO,_CLK_T_2B_1P,_LVDS2B_12P,_DQ17)
DDR4_DIMM_CH2_DQ43: J3.260(DQ43) U2.DA38(IO,_CLK_T_2B_1N,_LVDS2B_12N,_DQ17)
DDR4_DIMM_CH2_DQ44: J3.106(DQ44) U2.DC42(IO,_LVDS2B_8P,_DQ17)
DDR4_DIMM_CH2_DQ45: J3.251(DQ45) U2.DB43(IO,_LVDS2B_7P,_DQ17)
DDR4_DIMM_CH2_DQ46: J3.113(DQ46) U2.DA42(IO,_LVDS2B_8N,_DQ17)
DDR4_DIMM_CH2_DQ47: J3.258(DQ47) U2.CY43(IO,_LVDS2B_7N,_DQ17)
DDR4_DIMM_CH2_DQ48: J3.119(DQ48) U2.DA32(IO,_LVDS2B_23N,_DQ19)
DDR4_DIMM_CH2_DQ49: J3.264(DQ49) U2.DC32(IO,_LVDS2B_23P,_DQ19)
DDR4_DIMM_CH2_DQ50: J3.126(DQ50) U2.DB31(IO,_LVDS2B_24P,_DQ19)
DDR4_DIMM_CH2_DQ51: J3.271(DQ51) U2.CY31(IO,_LVDS2B_24N,_DQ19)
DDR4_DIMM_CH2_DQ52: J3.117(DQ52) U2.DA36(IO,_LVDS2B_19N,_DQ19)
DDR4_DIMM_CH2_DQ53: J3.262(DQ53) U2.DC36(IO,_LVDS2B_19P,_DQ19)
DDR4_DIMM_CH2_DQ54: J3.124(DQ54) U2.DB35(IO,_LVDS2B_20P,_DQ19)
DDR4_DIMM_CH2_DQ55: J3.269(DQ55) U2.CY35(IO,_LVDS2B_20N,_DQ19)
DDR4_DIMM_CH2_DQ56: J3.130(DQ56) U2.CR32(IO,_LVDS2B_17N,_DQ18)
DDR4_DIMM_CH2_DQ57: J3.275(DQ57) U2.CU32(IO,_LVDS2B_17P,_DQ18)
DDR4_DIMM_CH2_DQ58: J3.137(DQ58) U2.CV31(IO,_LVDS2B_18P,_DQ18)
DDR4_DIMM_CH2_DQ59: J3.282(DQ59) U2.CT31(IO,_LVDS2B_18N,_DQ18)
DDR4_DIMM_CH2_DQ60: J3.128(DQ60) U2.CV35(IO,_LVDS2B_14P,_DQ18)
DDR4_DIMM_CH2_DQ61: J3.273(DQ61) U2.CU36(IO,_CLK_T_2B_0P,_LVDS2B_13P,_DQ18)
DDR4_DIMM_CH2_DQ62: J3.135(DQ62) U2.CT35(IO,_LVDS2B_14N,_DQ18)
DDR4_DIMM_CH2_DQ63: J3.280(DQ63) U2.CR36(IO,_CLK_T_2B_0N,_LVDS2B_13N,_DQ18)
DDR4_DIMM_CH2_DQ64: J3.49(CB0/NC) U2.CU46(IO,_LVDS2A_17P,_DQ26)
DDR4_DIMM_CH2_DQ65: J3.194(CB1/NC) U2.CT45(IO,_LVDS2A_18N,_DQ26)
DDR4_DIMM_CH2_DQ66: J3.56(CB2/NC) U2.CR46(IO,_LVDS2A_17N,_DQ26)
DDR4_DIMM_CH2_DQ67: J3.201(CB3/NC) U2.CV45(IO,_LVDS2A_18P,_DQ26)
DDR4_DIMM_CH2_DQ68: J3.47(CB4/NC) U2.CT49(IO,_LVDS2A_14N,_DQ26)
DDR4_DIMM_CH2_DQ69: J3.192(CB5/NC) U2.CU50(IO,_CLK_T_2A_0P,_LVDS2A_13P,_DQ26)
DDR4_DIMM_CH2_DQ70: J3.54(CB6/NC) U2.CV49(IO,_LVDS2A_14P,_DQ26)
DDR4_DIMM_CH2_DQ71: J3.199(CB7/NC) U2.CR50(IO,_CLK_T_2A_0N,_LVDS2A_13N,_DQ26)
DDR4_DIMM_CH2_DQS_N0: J3.152(DQS0_c) U2.CE54(IO,_LVDS2A_28N,_DQSN28)
DDR4_DIMM_CH2_DQS_N1: J3.163(DQS1_c) U2.CR54(IO,_LVDS2A_4N,_DQSN24)
DDR4_DIMM_CH2_DQS_N2: J3.174(DQS2_c) U2.DA54(IO,_PLL_2A_T_CLKOUT1N,_LVDS2A_10N,_DQSN25)
DDR4_DIMM_CH2_DQS_N3: J3.185(DQS3_c) U2.CY47(IO,_LVDS2A_22N,_DQSN27)
DDR4_DIMM_CH2_DQS_N4: J3.244(DQS4_c) U2.CR40(IO,_LVDS2B_4N,_DQSN16)
DDR4_DIMM_CH2_DQS_N5: J3.255(DQS5_c) U2.DA40(IO,_PLL_2B_T_CLKOUT1N,_LVDS2B_10N,_DQSN17)
DDR4_DIMM_CH2_DQS_N6: J3.266(DQS6_c) U2.CY33(IO,_LVDS2B_22N,_DQSN19)
DDR4_DIMM_CH2_DQS_N7: J3.277(DQS7_c) U2.CT33(IO,_LVDS2B_16N,_DQSN18)
DDR4_DIMM_CH2_DQS_N8: J3.196(DQS8_c) U2.CT47(IO,_LVDS2A_16N,_DQSN26)
DDR4_DIMM_CH2_DQS_P0: J3.153(DQS0_t) U2.CG54(IO,_LVDS2A_28P,_DQS28)
DDR4_DIMM_CH2_DQS_P1: J3.164(DQS1_t) U2.CU54(IO,_LVDS2A_4P,_DQS24)
DDR4_DIMM_CH2_DQS_P2: J3.175(DQS2_t) U2.DC54(IO,_PLL_2A_T_CLKOUT1P,_PLL_2A_T_CLKOUT1,_PLL_2A_T_FB1,_LVDS2A_10P,_DQS25)
DDR4_DIMM_CH2_DQS_P3: J3.186(DQS3_t) U2.DB47(IO,_LVDS2A_22P,_DQS27)
DDR4_DIMM_CH2_DQS_P4: J3.245(DQS4_t) U2.CU40(IO,_LVDS2B_4P,_DQS16)
DDR4_DIMM_CH2_DQS_P5: J3.256(DQS5_t) U2.DC40(IO,_PLL_2B_T_CLKOUT1P,_PLL_2B_T_CLKOUT1,_PLL_2B_T_FB1,_LVDS2B_10P,_DQS17)
DDR4_DIMM_CH2_DQS_P6: J3.267(DQS6_t) U2.DB33(IO,_LVDS2B_22P,_DQS19)
DDR4_DIMM_CH2_DQS_P7: J3.278(DQS7_t) U2.CV33(IO,_LVDS2B_16P,_DQS18)
DDR4_DIMM_CH2_DQS_P8: J3.197(DQS8_t) U2.CV47(IO,_LVDS2A_16P,_DQS26)
DDR4_DIMM_CH2_ODT0: J3.87(ODT0) U2.CM33(IO,_LVDS2B_46P,_DQS23)
DDR4_DIMM_CH2_ODT1: J3.91(ODT1) U2.CK33(IO,_LVDS2B_46N,_DQSN23)
DDR4_DIMM_CH2_PAR: J3.222(PARITY) U2.CL36(IO,_LVDS2B_43N,_DQ23)
DDR4_DIMM_CH2_RESET_N: J3.58(RESET_n) R61.1 R62.2 U2.CK31(IO,_LVDS2B_48N,_DQ23)
DDR4_DIMM_CH2_RZQ: R66.2 U2.CM39(IO,_RZQ_B_2B,_LVDS2B_35P,_DQ21)
DDR4_DIMM_CH2_SA0: J3.139(SA0) R58.2
DDR4_DIMM_CH2_SA1: J3.140(SA1) R59.1
DDR4_DIMM_CH2_SA2: J3.238(SA2/RFU) R60.2
DDR4_DIMM_CH2_TDQS_N9: J3.8(DQS9_c) U2.CF55(IO,_LVDS2A_27N,_DQ28)
DDR4_DIMM_CH2_TDQS_N10: J3.19(DQS10_c) U2.CT55(IO,_LVDS2A_3N,_DQ24)
DDR4_DIMM_CH2_TDQS_N11: J3.30(DQS11_c) U2.CY55(IO,_LVDS2A_9N,_DQ25)
DDR4_DIMM_CH2_TDQS_N12: J3.41(DQS12_c) U2.DA48(IO,_LVDS2A_21N,_DQ27)
DDR4_DIMM_CH2_TDQS_N13: J3.100(DQS13_c) U2.CT41(IO,_LVDS2B_3N,_DQ16)
DDR4_DIMM_CH2_TDQS_N14: J3.111(DQS14_c) U2.CY41(IO,_LVDS2B_9N,_DQ17)
DDR4_DIMM_CH2_TDQS_N15: J3.122(DQS15_c) U2.DA34(IO,_LVDS2B_21N,_DQ19)
DDR4_DIMM_CH2_TDQS_N16: J3.133(DQS16_c) U2.CR34(IO,_PLL_2B_T_CLKOUT0N,_LVDS2B_15N,_DQ18)
DDR4_DIMM_CH2_TDQS_N17: J3.52(DQS17_c) U2.CR48(IO,_PLL_2A_T_CLKOUT0N,_LVDS2A_15N,_DQ26)
DDR4_DIMM_CH3_A0: J4.79(A0) ; also on sheet 20
DDR4_DIMM_CH3_A1: J4.72(A1) ; also on sheet 20
DDR4_DIMM_CH3_A2: J4.216(A2) ; also on sheet 20
DDR4_DIMM_CH3_A3: J4.71(A3) ; also on sheet 20
DDR4_DIMM_CH3_A4: J4.214(A4) ; also on sheet 20
DDR4_DIMM_CH3_A5: J4.213(A5) ; also on sheet 20
DDR4_DIMM_CH3_A6: J4.69(A6) ; also on sheet 20
DDR4_DIMM_CH3_A7: J4.211(A7) ; also on sheet 20
DDR4_DIMM_CH3_A8: J4.68(A8) ; also on sheet 20
DDR4_DIMM_CH3_A9: J4.66(A9) ; also on sheet 20
DDR4_DIMM_CH3_A10: J4.225(A10/AP) ; also on sheet 20
DDR4_DIMM_CH3_A11: J4.210(A11) ; also on sheet 20
DDR4_DIMM_CH3_A12: J4.65(A12) ; also on sheet 20
DDR4_DIMM_CH3_A13: J4.232(A13) ; also on sheet 20
DDR4_DIMM_CH3_A14: J4.228(WE_n/A14) ; also on sheet 20
DDR4_DIMM_CH3_A15: J4.86(CAS_n/A15) ; also on sheet 20
DDR4_DIMM_CH3_A16: J4.82(RAS_n/A16) ; also on sheet 20
DDR4_DIMM_CH3_A17: J4.234(A17/NC) ; also on sheet 20
DDR4_DIMM_CH3_ACT_N: J4.62(ACT_n) ; also on sheet 20
DDR4_DIMM_CH3_ALERT_N: J4.208(ALERT_n) R792.1 ; also on sheet 20
DDR4_DIMM_CH3_BA0: J4.81(BA0) ; also on sheet 20
DDR4_DIMM_CH3_BA1: J4.224(BA1) ; also on sheet 20
DDR4_DIMM_CH3_BG0: J4.63(BG0) ; also on sheet 20
DDR4_DIMM_CH3_BG1: J4.207(BG1) ; also on sheet 20
DDR4_DIMM_CH3_C2: J4.235(C2/NC) ; also on sheet 20
DDR4_DIMM_CH3_CK_N0: J4.75(CK0_c) ; also on sheet 20
DDR4_DIMM_CH3_CK_N1: J4.219(CK1_c) ; also on sheet 20
DDR4_DIMM_CH3_CK_P0: J4.74(CK0_t) ; also on sheet 20
DDR4_DIMM_CH3_CK_P1: J4.218(CK1_t) ; also on sheet 20
DDR4_DIMM_CH3_CKE0: J4.60(CKE0) R77.2 ; also on sheet 20
DDR4_DIMM_CH3_CKE1: J4.203(CKE1) R78.2 ; also on sheet 20
DDR4_DIMM_CH3_CS_N0: J4.84(S0_n) ; also on sheet 20
DDR4_DIMM_CH3_CS_N1: J4.89(S1_n) ; also on sheet 20
DDR4_DIMM_CH3_CS_N2: J4.93(S2_n/C0) ; also on sheet 20
DDR4_DIMM_CH3_CS_N3: J4.237(S3_n/C1) ; also on sheet 20
DDR4_DIMM_CH3_DBI_N0: J4.7(DQS9_t/DM0_n/DBI0_n) ; also on sheet 19
DDR4_DIMM_CH3_DBI_N1: J4.18(DQS10_t/DM1_n/DBI1_n) ; also on sheet 19
DDR4_DIMM_CH3_DBI_N2: J4.29(DQS11_t/DM2_n/DBI2_n) ; also on sheet 19
DDR4_DIMM_CH3_DBI_N3: J4.40(DQS12_t/DM3_n/DBI3_n) ; also on sheet 19
DDR4_DIMM_CH3_DBI_N4: J4.99(DQS13_t/DM4_n/DBI4_n) ; also on sheet 20
DDR4_DIMM_CH3_DBI_N5: J4.110(DQS14_t/DM5_n/DBI5_n) ; also on sheet 20
DDR4_DIMM_CH3_DBI_N6: J4.121(DQS15_t/DM6_n/DBI6_n) ; also on sheet 20
DDR4_DIMM_CH3_DBI_N7: J4.132(DQS16_t/DM7_n/DBI7_n) ; also on sheet 20
DDR4_DIMM_CH3_DBI_N8: J4.51(DQS17_t/DM8_n/DBI8_n) ; also on sheet 19
DDR4_DIMM_CH3_DQ0: J4.5(DQ0) ; also on sheet 19
DDR4_DIMM_CH3_DQ1: J4.150(DQ1) ; also on sheet 19
DDR4_DIMM_CH3_DQ2: J4.12(DQ2) ; also on sheet 19
DDR4_DIMM_CH3_DQ3: J4.157(DQ3) ; also on sheet 19
DDR4_DIMM_CH3_DQ4: J4.3(DQ4) ; also on sheet 19
DDR4_DIMM_CH3_DQ5: J4.148(DQ5) ; also on sheet 19
DDR4_DIMM_CH3_DQ6: J4.10(DQ6) ; also on sheet 19
DDR4_DIMM_CH3_DQ7: J4.155(DQ7) ; also on sheet 19
DDR4_DIMM_CH3_DQ8: J4.16(DQ8) ; also on sheet 19
DDR4_DIMM_CH3_DQ9: J4.161(DQ9) ; also on sheet 19
DDR4_DIMM_CH3_DQ10: J4.23(DQ10) ; also on sheet 19
DDR4_DIMM_CH3_DQ11: J4.168(DQ11) ; also on sheet 19
DDR4_DIMM_CH3_DQ12: J4.14(DQ12) ; also on sheet 19
DDR4_DIMM_CH3_DQ13: J4.159(DQ13) ; also on sheet 19
DDR4_DIMM_CH3_DQ14: J4.21(DQ14) ; also on sheet 19
DDR4_DIMM_CH3_DQ15: J4.166(DQ15) ; also on sheet 19
DDR4_DIMM_CH3_DQ16: J4.27(DQ16) ; also on sheet 19
DDR4_DIMM_CH3_DQ17: J4.172(DQ17) ; also on sheet 19
DDR4_DIMM_CH3_DQ18: J4.34(DQ18) ; also on sheet 19
DDR4_DIMM_CH3_DQ19: J4.179(DQ19) ; also on sheet 19
DDR4_DIMM_CH3_DQ20: J4.25(DQ20) ; also on sheet 19
DDR4_DIMM_CH3_DQ21: J4.170(DQ21) ; also on sheet 19
DDR4_DIMM_CH3_DQ22: J4.32(DQ22) ; also on sheet 19
DDR4_DIMM_CH3_DQ23: J4.177(DQ23) ; also on sheet 19
DDR4_DIMM_CH3_DQ24: J4.38(DQ24) ; also on sheet 19
DDR4_DIMM_CH3_DQ25: J4.183(DQ25) ; also on sheet 19
DDR4_DIMM_CH3_DQ26: J4.45(DQ26) ; also on sheet 19
DDR4_DIMM_CH3_DQ27: J4.190(DQ27) ; also on sheet 19
DDR4_DIMM_CH3_DQ28: J4.36(DQ28) ; also on sheet 19
DDR4_DIMM_CH3_DQ29: J4.181(DQ29) ; also on sheet 19
DDR4_DIMM_CH3_DQ30: J4.43(DQ30) ; also on sheet 19
DDR4_DIMM_CH3_DQ31: J4.188(DQ31) ; also on sheet 19
DDR4_DIMM_CH3_DQ32: J4.97(DQ32) ; also on sheet 20
DDR4_DIMM_CH3_DQ33: J4.242(DQ33) ; also on sheet 20
DDR4_DIMM_CH3_DQ34: J4.104(DQ34) ; also on sheet 20
DDR4_DIMM_CH3_DQ35: J4.249(DQ35) ; also on sheet 20
DDR4_DIMM_CH3_DQ36: J4.95(DQ36) ; also on sheet 20
DDR4_DIMM_CH3_DQ37: J4.240(DQ37) ; also on sheet 20
DDR4_DIMM_CH3_DQ38: J4.102(DQ38) ; also on sheet 20
DDR4_DIMM_CH3_DQ39: J4.247(DQ39) ; also on sheet 20
DDR4_DIMM_CH3_DQ40: J4.108(DQ40) ; also on sheet 20
DDR4_DIMM_CH3_DQ41: J4.253(DQ41) ; also on sheet 20
DDR4_DIMM_CH3_DQ42: J4.115(DQ42) ; also on sheet 20
DDR4_DIMM_CH3_DQ43: J4.260(DQ43) ; also on sheet 20
DDR4_DIMM_CH3_DQ44: J4.106(DQ44) ; also on sheet 20
DDR4_DIMM_CH3_DQ45: J4.251(DQ45) ; also on sheet 20
DDR4_DIMM_CH3_DQ46: J4.113(DQ46) ; also on sheet 20
DDR4_DIMM_CH3_DQ47: J4.258(DQ47) ; also on sheet 20
DDR4_DIMM_CH3_DQ48: J4.119(DQ48) ; also on sheet 20
DDR4_DIMM_CH3_DQ49: J4.264(DQ49) ; also on sheet 20
DDR4_DIMM_CH3_DQ50: J4.126(DQ50) ; also on sheet 20
DDR4_DIMM_CH3_DQ51: J4.271(DQ51) ; also on sheet 20
DDR4_DIMM_CH3_DQ52: J4.117(DQ52) ; also on sheet 20
DDR4_DIMM_CH3_DQ53: J4.262(DQ53) ; also on sheet 20
DDR4_DIMM_CH3_DQ54: J4.124(DQ54) ; also on sheet 20
DDR4_DIMM_CH3_DQ55: J4.269(DQ55) ; also on sheet 20
DDR4_DIMM_CH3_DQ56: J4.130(DQ56) ; also on sheet 20
DDR4_DIMM_CH3_DQ57: J4.275(DQ57) ; also on sheet 20
DDR4_DIMM_CH3_DQ58: J4.137(DQ58) ; also on sheet 20
DDR4_DIMM_CH3_DQ59: J4.282(DQ59) ; also on sheet 20
DDR4_DIMM_CH3_DQ60: J4.128(DQ60) ; also on sheet 20
DDR4_DIMM_CH3_DQ61: J4.273(DQ61) ; also on sheet 20
DDR4_DIMM_CH3_DQ62: J4.135(DQ62) ; also on sheet 20
DDR4_DIMM_CH3_DQ63: J4.280(DQ63) ; also on sheet 20
DDR4_DIMM_CH3_DQ64: J4.49(CB0/NC) ; also on sheet 19
DDR4_DIMM_CH3_DQ65: J4.194(CB1/NC) ; also on sheet 19
DDR4_DIMM_CH3_DQ66: J4.56(CB2/NC) ; also on sheet 19
DDR4_DIMM_CH3_DQ67: J4.201(CB3/NC) ; also on sheet 19
DDR4_DIMM_CH3_DQ68: J4.47(CB4/NC) ; also on sheet 19
DDR4_DIMM_CH3_DQ69: J4.192(CB5/NC) ; also on sheet 19
DDR4_DIMM_CH3_DQ70: J4.54(CB6/NC) ; also on sheet 19
DDR4_DIMM_CH3_DQ71: J4.199(CB7/NC) ; also on sheet 19
DDR4_DIMM_CH3_DQS_N0: J4.152(DQS0_c) ; also on sheet 19
DDR4_DIMM_CH3_DQS_N1: J4.163(DQS1_c) ; also on sheet 19
DDR4_DIMM_CH3_DQS_N2: J4.174(DQS2_c) ; also on sheet 19
DDR4_DIMM_CH3_DQS_N3: J4.185(DQS3_c) ; also on sheet 19
DDR4_DIMM_CH3_DQS_N4: J4.244(DQS4_c) ; also on sheet 20
DDR4_DIMM_CH3_DQS_N5: J4.255(DQS5_c) ; also on sheet 20
DDR4_DIMM_CH3_DQS_N6: J4.266(DQS6_c) ; also on sheet 20
DDR4_DIMM_CH3_DQS_N7: J4.277(DQS7_c) ; also on sheet 20
DDR4_DIMM_CH3_DQS_N8: J4.196(DQS8_c) ; also on sheet 19
DDR4_DIMM_CH3_DQS_P0: J4.153(DQS0_t) ; also on sheet 19
DDR4_DIMM_CH3_DQS_P1: J4.164(DQS1_t) ; also on sheet 19
DDR4_DIMM_CH3_DQS_P2: J4.175(DQS2_t) ; also on sheet 19
DDR4_DIMM_CH3_DQS_P3: J4.186(DQS3_t) ; also on sheet 19
DDR4_DIMM_CH3_DQS_P4: J4.245(DQS4_t) ; also on sheet 20
DDR4_DIMM_CH3_DQS_P5: J4.256(DQS5_t) ; also on sheet 20
DDR4_DIMM_CH3_DQS_P6: J4.267(DQS6_t) ; also on sheet 20
DDR4_DIMM_CH3_DQS_P7: J4.278(DQS7_t) ; also on sheet 20
DDR4_DIMM_CH3_DQS_P8: J4.197(DQS8_t) ; also on sheet 19
DDR4_DIMM_CH3_ODT0: J4.87(ODT0) ; also on sheet 20
DDR4_DIMM_CH3_ODT1: J4.91(ODT1) ; also on sheet 20
DDR4_DIMM_CH3_PAR: J4.222(PARITY) ; also on sheet 20
DDR4_DIMM_CH3_RESET_N: J4.58(RESET_n) R75.1 R76.2 ; also on sheet 20
DDR4_DIMM_CH3_SA0: J4.139(SA0) R72.1
DDR4_DIMM_CH3_SA1: J4.140(SA1) R73.1
DDR4_DIMM_CH3_SA2: J4.238(SA2/RFU) R74.2
DDR4_DIMM_CH3_TDQS_N9: J4.8(DQS9_c) ; also on sheet 19
DDR4_DIMM_CH3_TDQS_N10: J4.19(DQS10_c) ; also on sheet 19
DDR4_DIMM_CH3_TDQS_N11: J4.30(DQS11_c) ; also on sheet 19
DDR4_DIMM_CH3_TDQS_N12: J4.41(DQS12_c) ; also on sheet 19
DDR4_DIMM_CH3_TDQS_N13: J4.100(DQS13_c) ; also on sheet 20
DDR4_DIMM_CH3_TDQS_N14: J4.111(DQS14_c) ; also on sheet 20
DDR4_DIMM_CH3_TDQS_N15: J4.122(DQS15_c) ; also on sheet 20
DDR4_DIMM_CH3_TDQS_N16: J4.133(DQS16_c) ; also on sheet 20
DDR4_DIMM_CH3_TDQS_N17: J4.52(DQS17_c) ; also on sheet 19
DDR4D_SCL: J3.141(SCL) J4.141(SCL) ; also on sheet 9 12
DDR4D_SDA: J3.285(SDA) J4.285(SDA) ; also on sheet 9 12
N35351327: J3.1(12V/NC) J3.145(12V/NC) R54.2 R55.2
N35351465: J3.288(Vpp) R65.2
N35410578: J4.1(12V/NC) J4.145(12V/NC) R68.2 R69.2
N35410716: J4.288(Vpp) R79.2

Not connected (* = marked no-connect by the designer): J3 144(RFU1)* 205(RFU2)* 227(RFU3)*; J4 144(RFU1)* 205(RFU2)* 227(RFU3)*; U2 CE40(IO,_LVDS2B_28N,_DQSN20)* CE42(IO,_LVDS2B_26N,_DQ20)* CE46(IO,_LVDS2A_41N,_DQ30)* CE48(IO,_PLL_2A_B_CLKOUT0N,_LVDS2A_39N,_DQ30)* CE50(IO,_CLK_B_2A_0N,_LVDS2A_37N,_DQ30)* CF39(IO,_LVDS2B_29N,_DQ20)* CF41(IO,_LVDS2B_27N,_DQ20)* CF45(IO,_LVDS2A_42N,_DQ30)* CF47(IO,_LVDS2A_40N,_DQSN30)* CF49(IO,_LVDS2A_38N,_DQ30)* CG40(IO,_LVDS2B_28P,_DQS20)* CG46(IO,_LVDS2A_41P,_DQ30)* CG48(IO,_PLL_2A_B_CLKOUT0P,_PLL_2A_B_CLKOUT0,_PLL_2A_B_FB0,_LVDS2A_39P,_DQ30)* CG50(IO,_CLK_B_2A_0P,_LVDS2A_37P,_DQ30)* CH41(IO,_LVDS2B_27P,_DQ20)* CH45(IO,_LVDS2A_42P,_DQ30)* CH47(IO,_LVDS2A_40P,_DQS30)* CH49(IO,_LVDS2A_38P,_DQ30)* CK47(IO,_LVDS2A_46N,_DQSN31)* CK49(IO,_LVDS2A_44N,_DQ31)* CK53(IO,_LVDS2A_35N,_DQ29)* CK55(IO,_LVDS2A_33N,_DQ29)* CK57(IO,_LVDS2A_31N,_DQ29)* CL48(IO,_LVDS2A_45N,_DQ31)* CL50(IO,_LVDS2A_43N,_DQ31)* CL52(IO,_CLK_B_2A_1N,_LVDS2A_36N,_DQ29)* CL54(IO,_PLL_2A_B_CLKOUT1N,_LVDS2A_34N,_DQSN29)* CL56(IO,_LVDS2A_32N,_DQ29)* CM47(IO,_LVDS2A_46P,_DQS31)* CM49(IO,_LVDS2A_44P,_DQ31)* CM53(IO,_RZQ_B_2A,_LVDS2A_35P,_DQ29)* CM55(IO,_LVDS2A_33P,_DQ29)* CM57(IO,_LVDS2A_31P,_DQ29)* CN48(IO,_LVDS2A_45P,_DQ31)* CN50(IO,_LVDS2A_43P,_DQ31)* CN52(IO,_CLK_B_2A_1P,_LVDS2A_36P,_DQ29)* CN54(IO,_PLL_2A_B_CLKOUT1P,_PLL_2A_B_CLKOUT1,_PLL_2A_B_FB1,_LVDS2A_34P,_DQS29)* CN56(IO,_LVDS2A_32P,_DQ29)*; U4 6(NC0)* 9(NC1)*

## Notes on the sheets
sheet 15
- DDR4/DDRT Single DIMM CH2
- x72bit DIMM Only
- DDR4 DIMM IF
- I2C Addr: 0xA4
- Put caps on VDD pins which are close to DIMM A/C pins
sheet 16
- DDR4/T CH2 INTERFACE -- FPGA SIDE 2A
sheet 17
- DDR4/T CH2 INTERFACE -- FPGA SIDE 2B
- DDRT:ERID2
- DDRT:ERID0
- DDRT:NC
- DDRT:C2
- DDRT:C3
- DDRT:C1
- DDRT:GNT0
- DDRT:REQ
- DDRT:ERR
sheet 18
- DDR4/DDRT Single DIMM CH3
- x72bit DIMM Only
- DDR4 DIMM IF
- I2C Addr: 0xA6
- Put caps on VDD pins which are close to DIMM A/C pins
